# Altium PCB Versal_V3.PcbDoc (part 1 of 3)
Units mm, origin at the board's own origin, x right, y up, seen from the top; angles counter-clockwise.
Board outline 164.5 x 88.9 mm, 8 copper layers (Top Layer, Layer 2 [GND], Layer 3 [GND/OUT], Layer 4 [12V/GND], Layer 5 [GND/VOUT], Layer 6 [GND], Layer 7 [GND], Bottom Layer), stack 1.562 mm thick; 243 components, 69 nets, 695 pads, 1061 vias.
Unrouted connection lines stored in the file: 8.
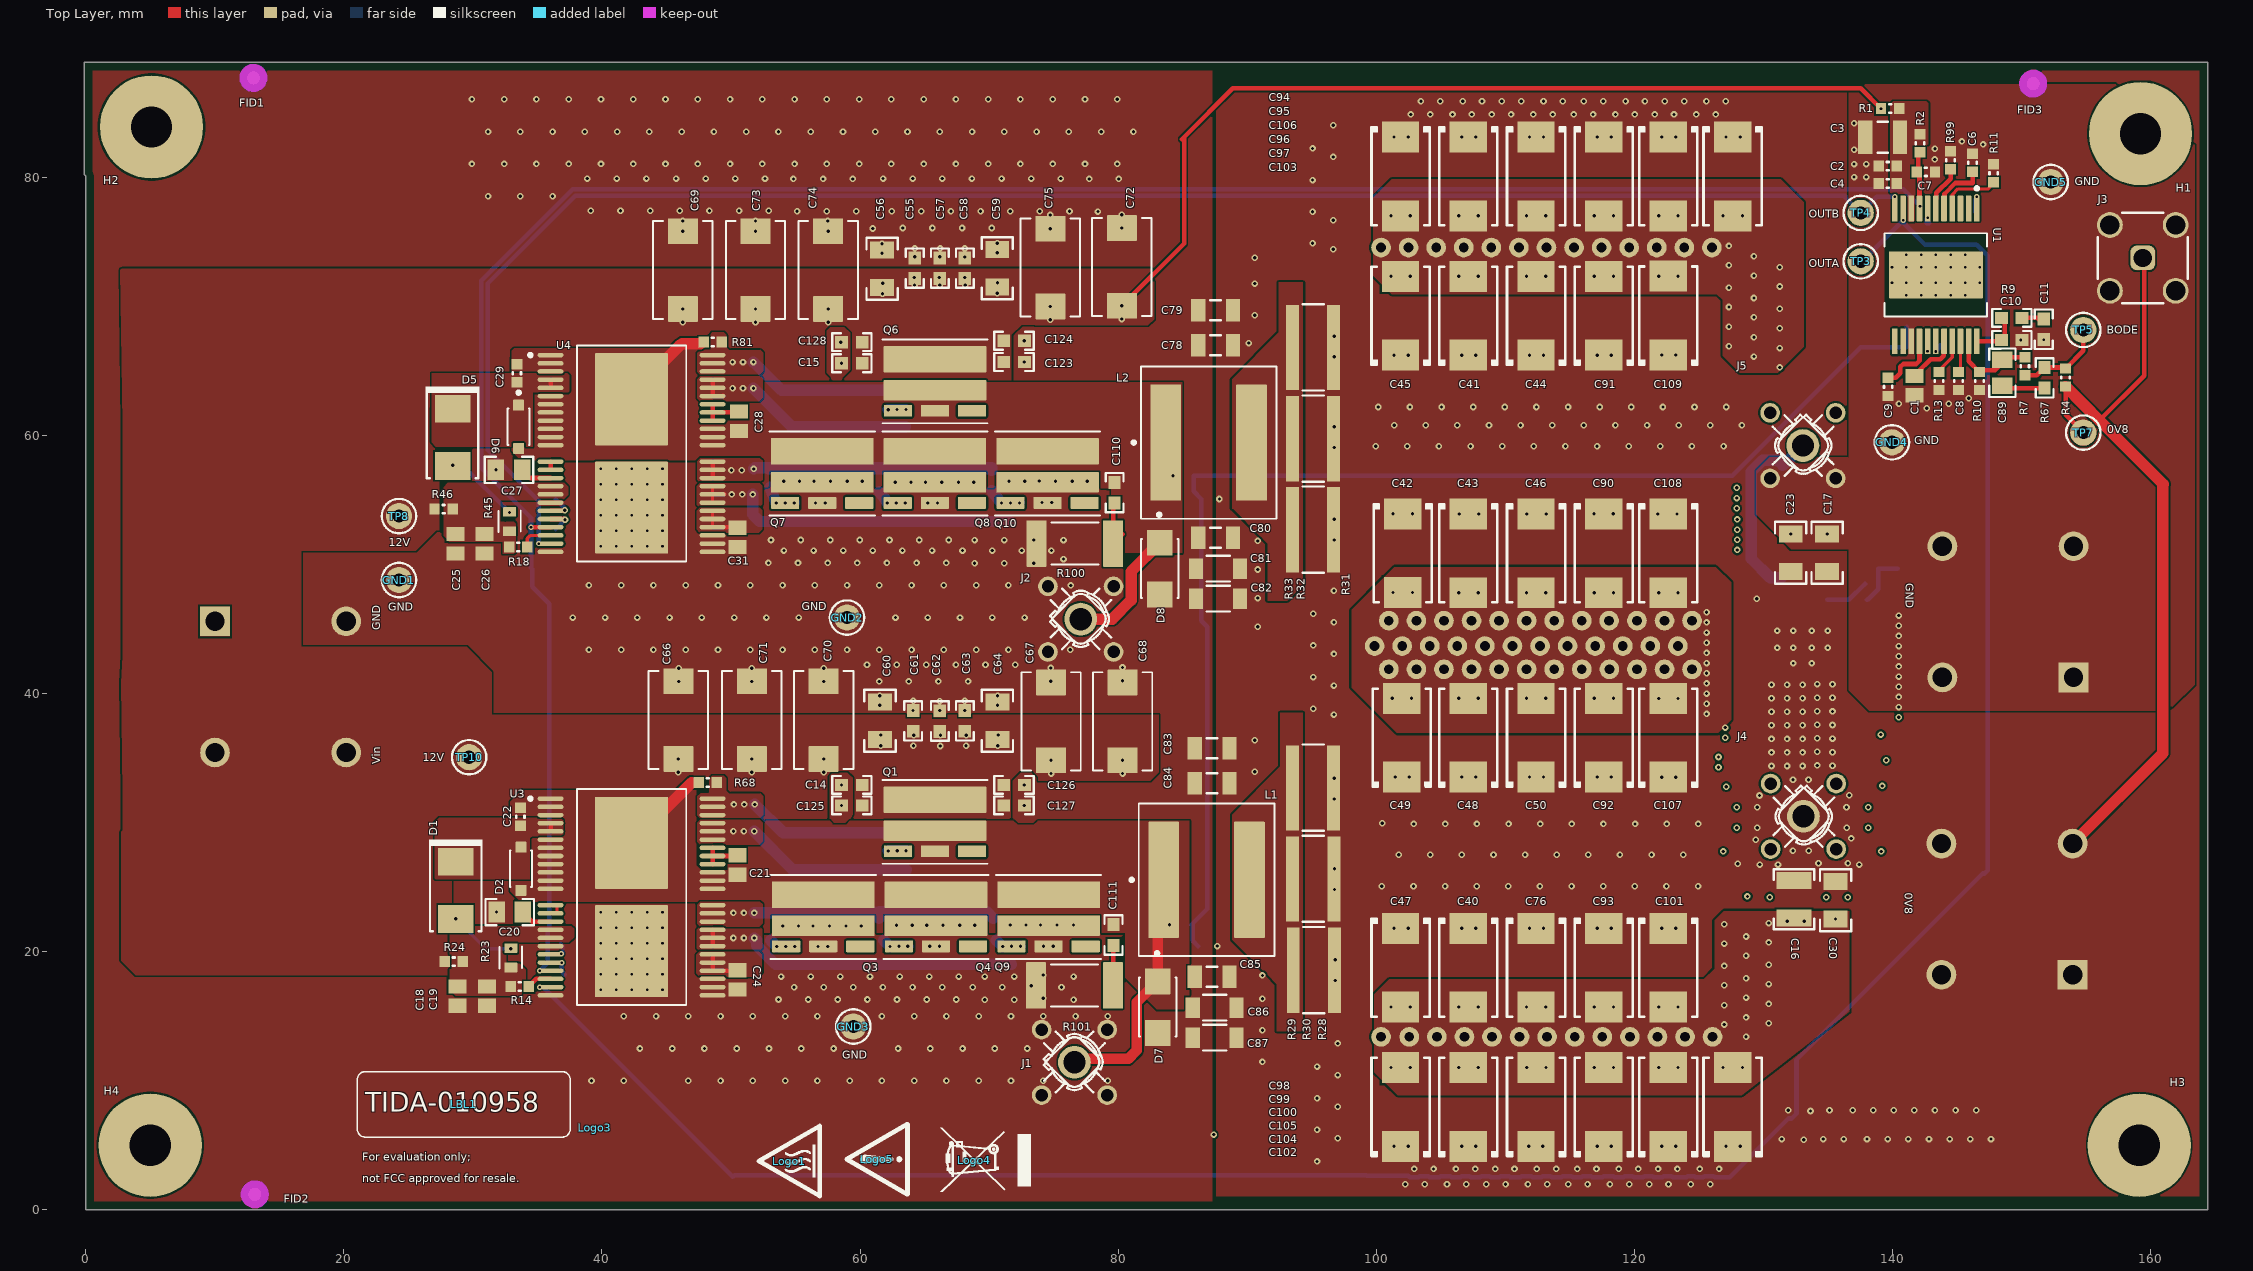
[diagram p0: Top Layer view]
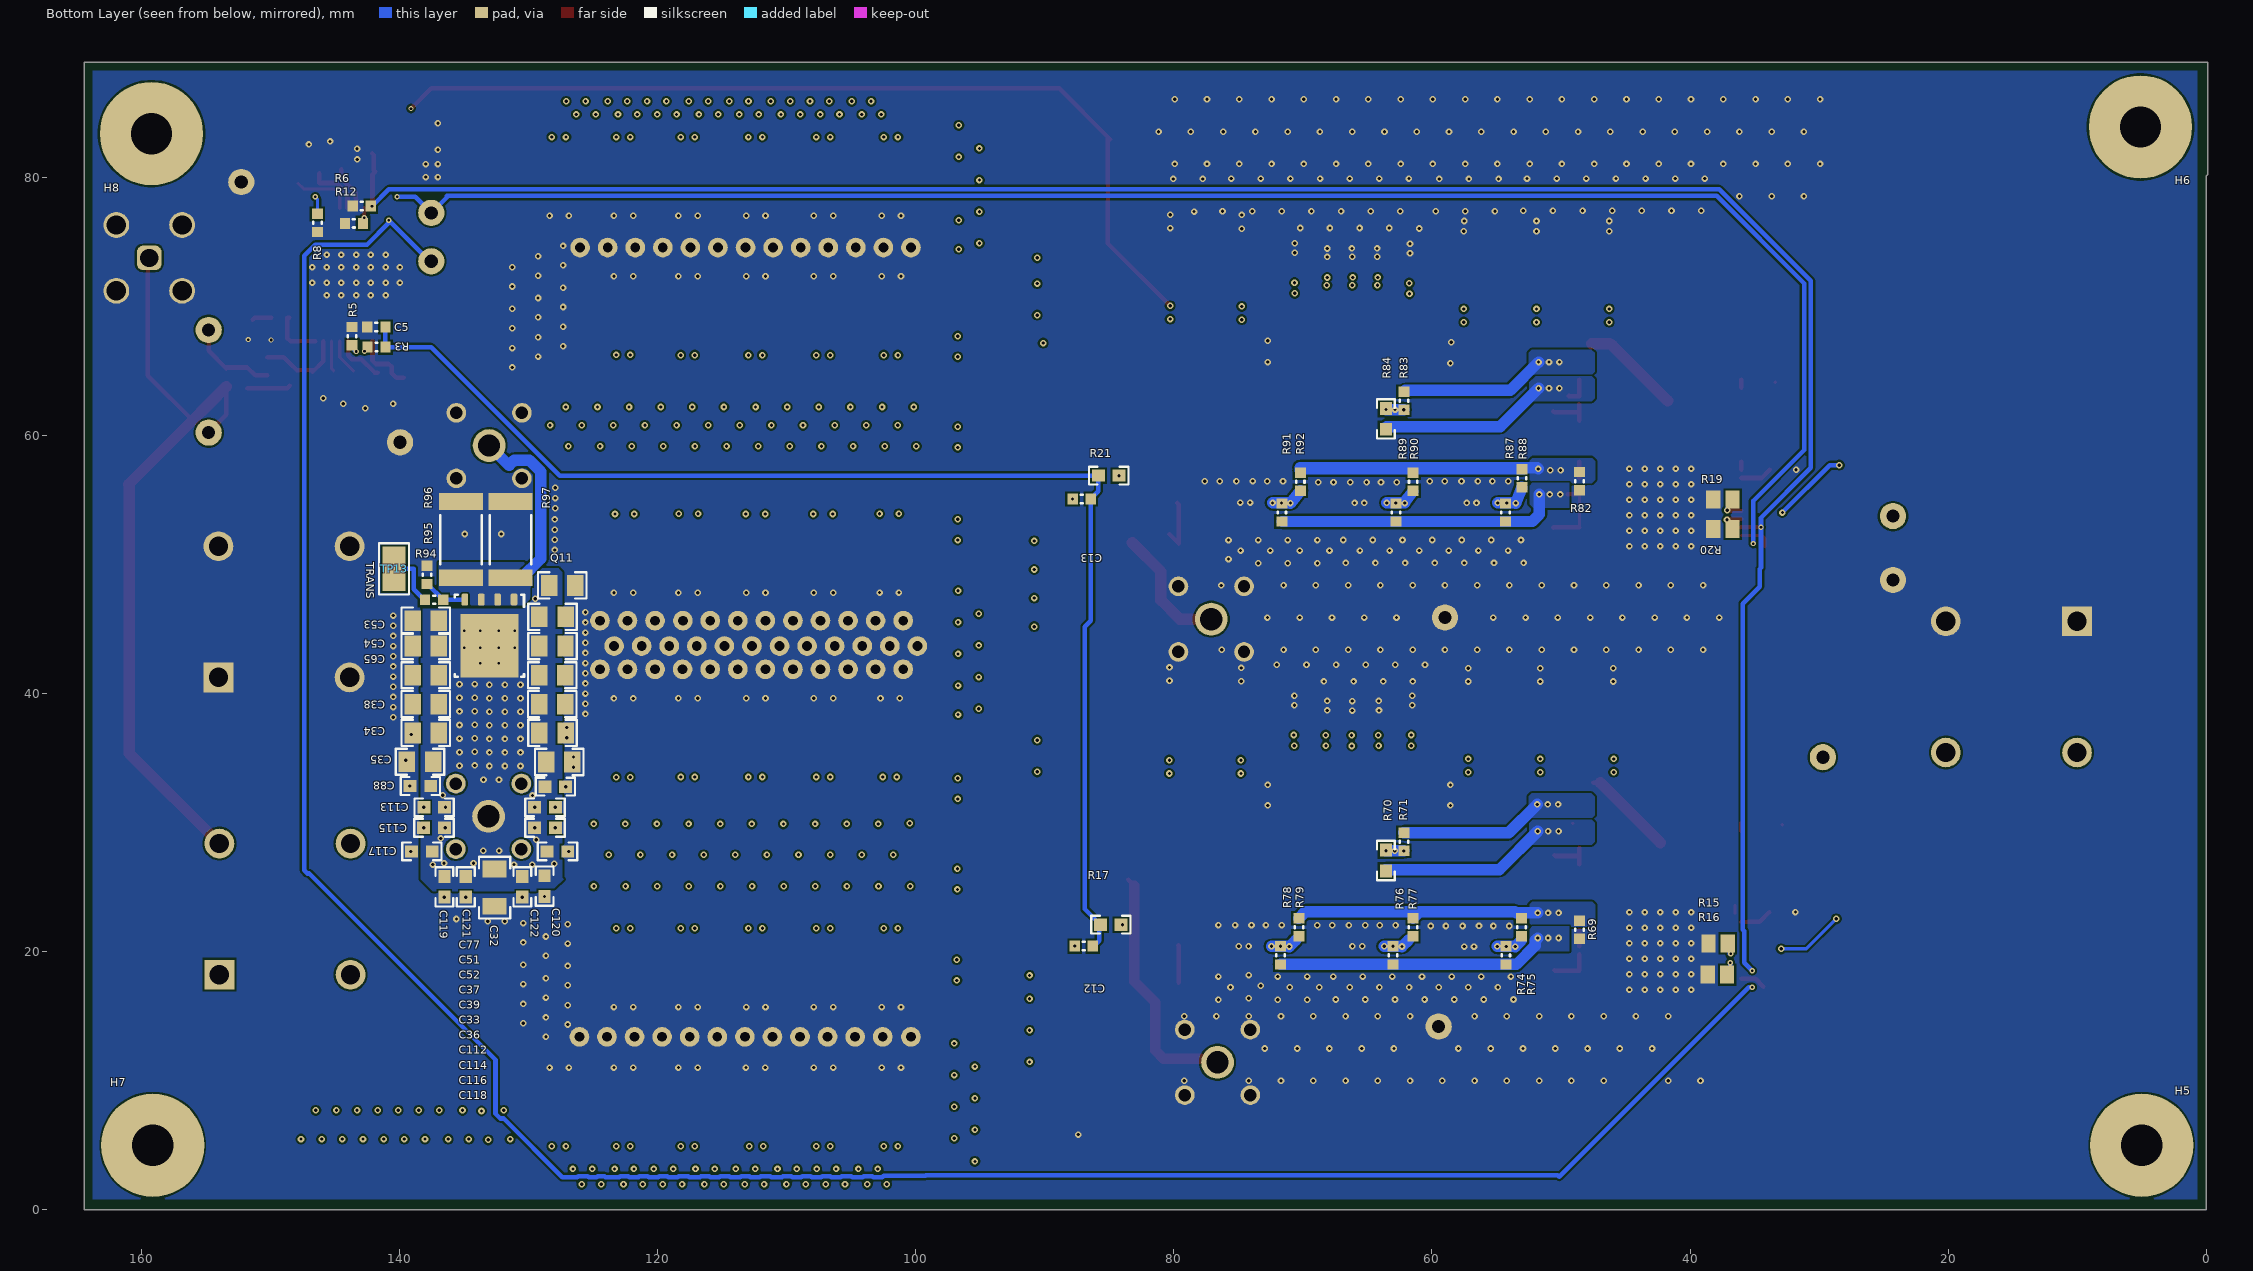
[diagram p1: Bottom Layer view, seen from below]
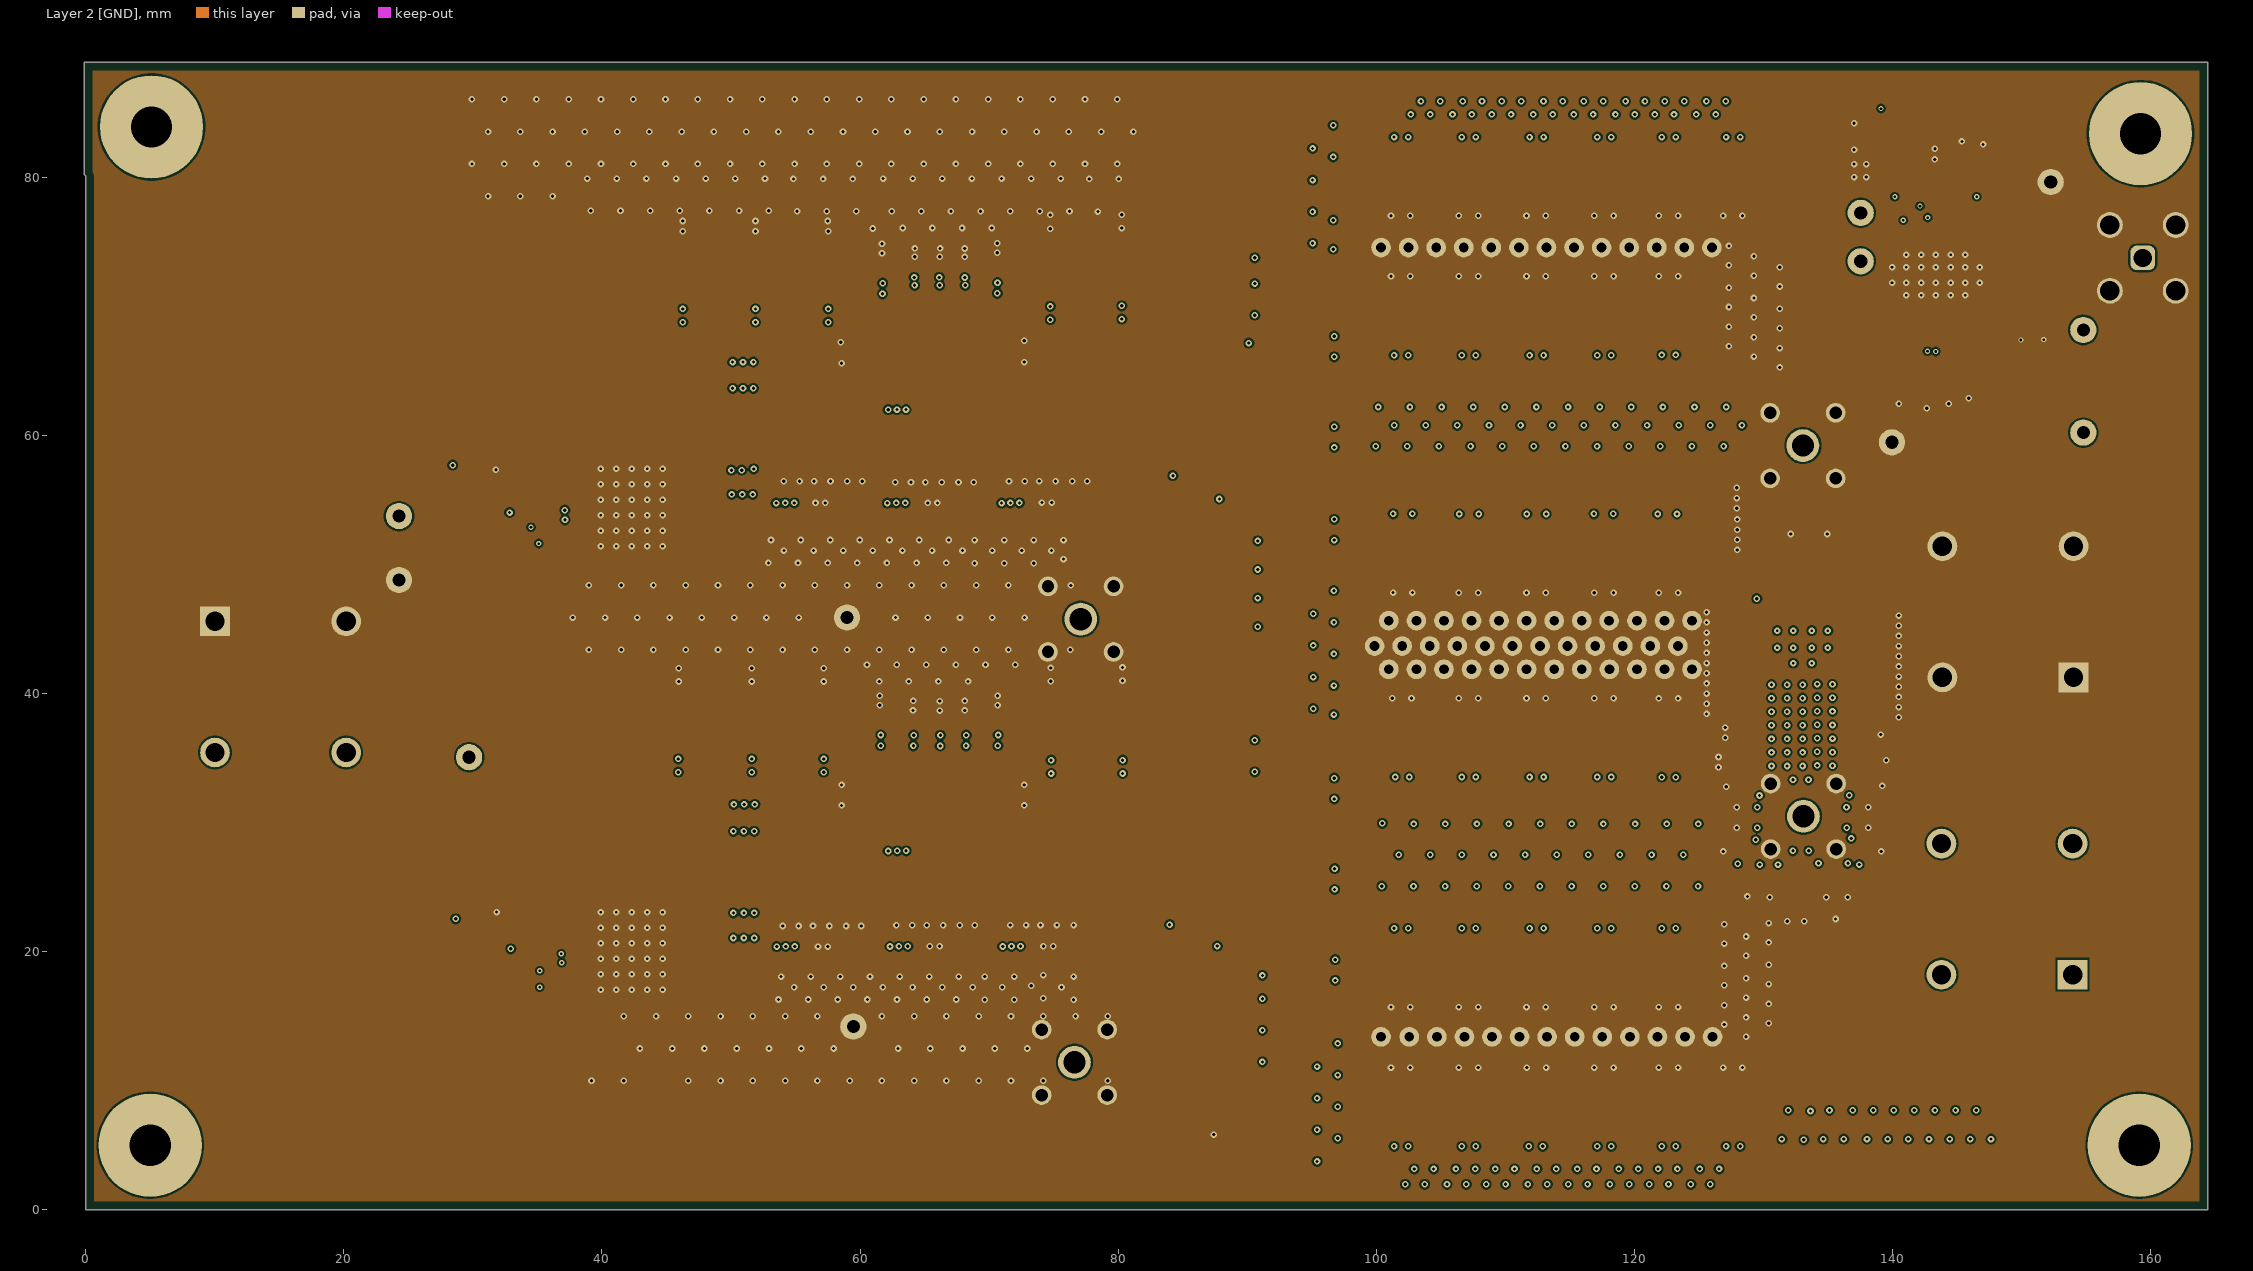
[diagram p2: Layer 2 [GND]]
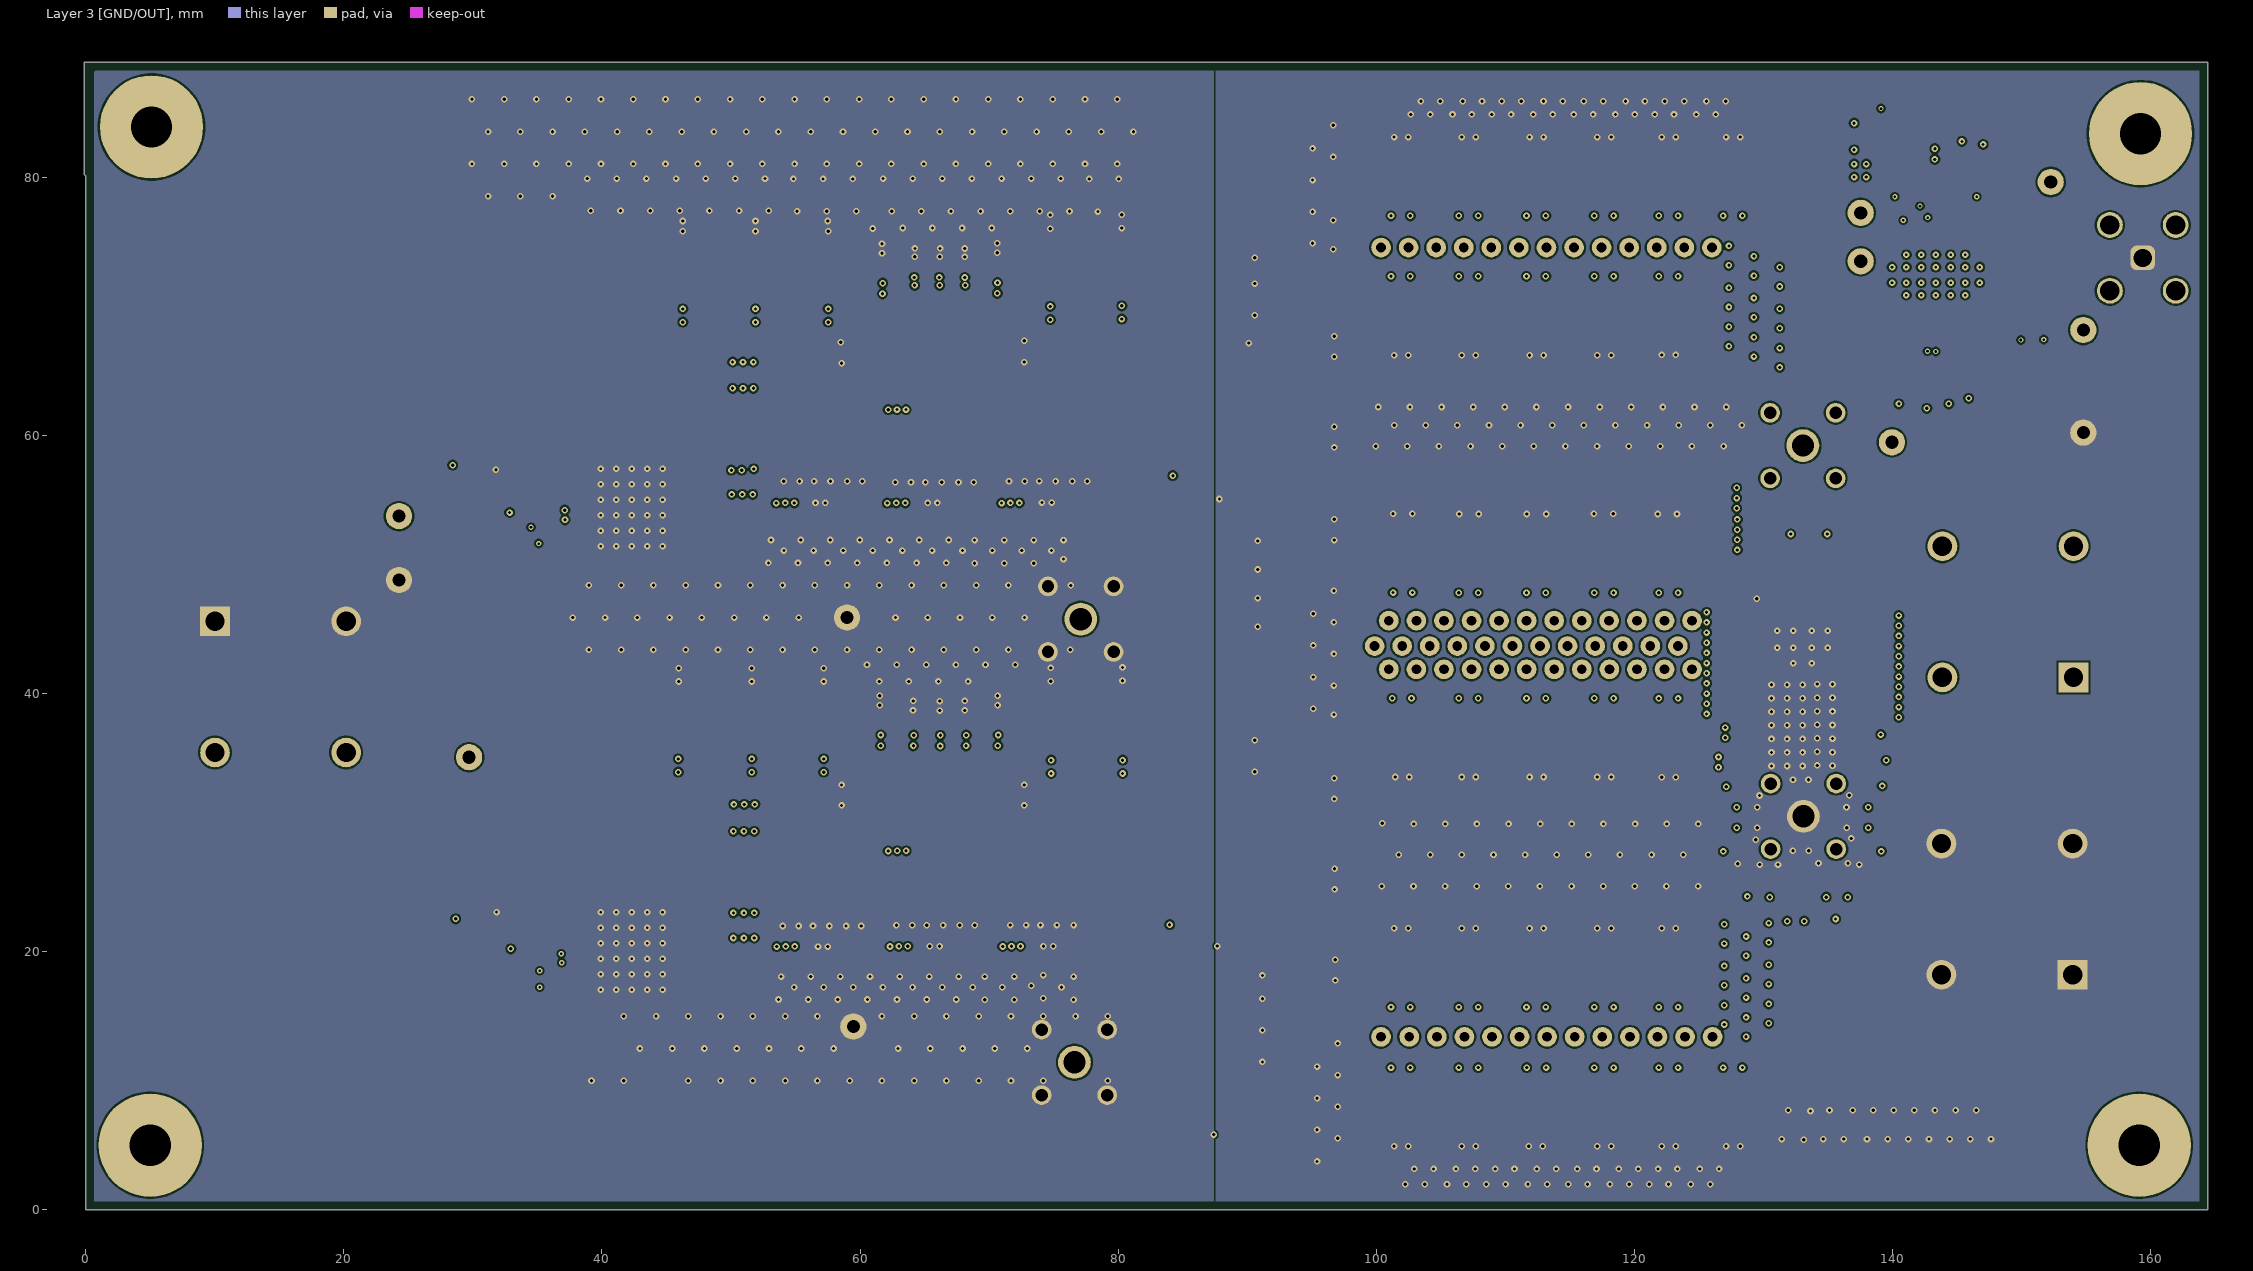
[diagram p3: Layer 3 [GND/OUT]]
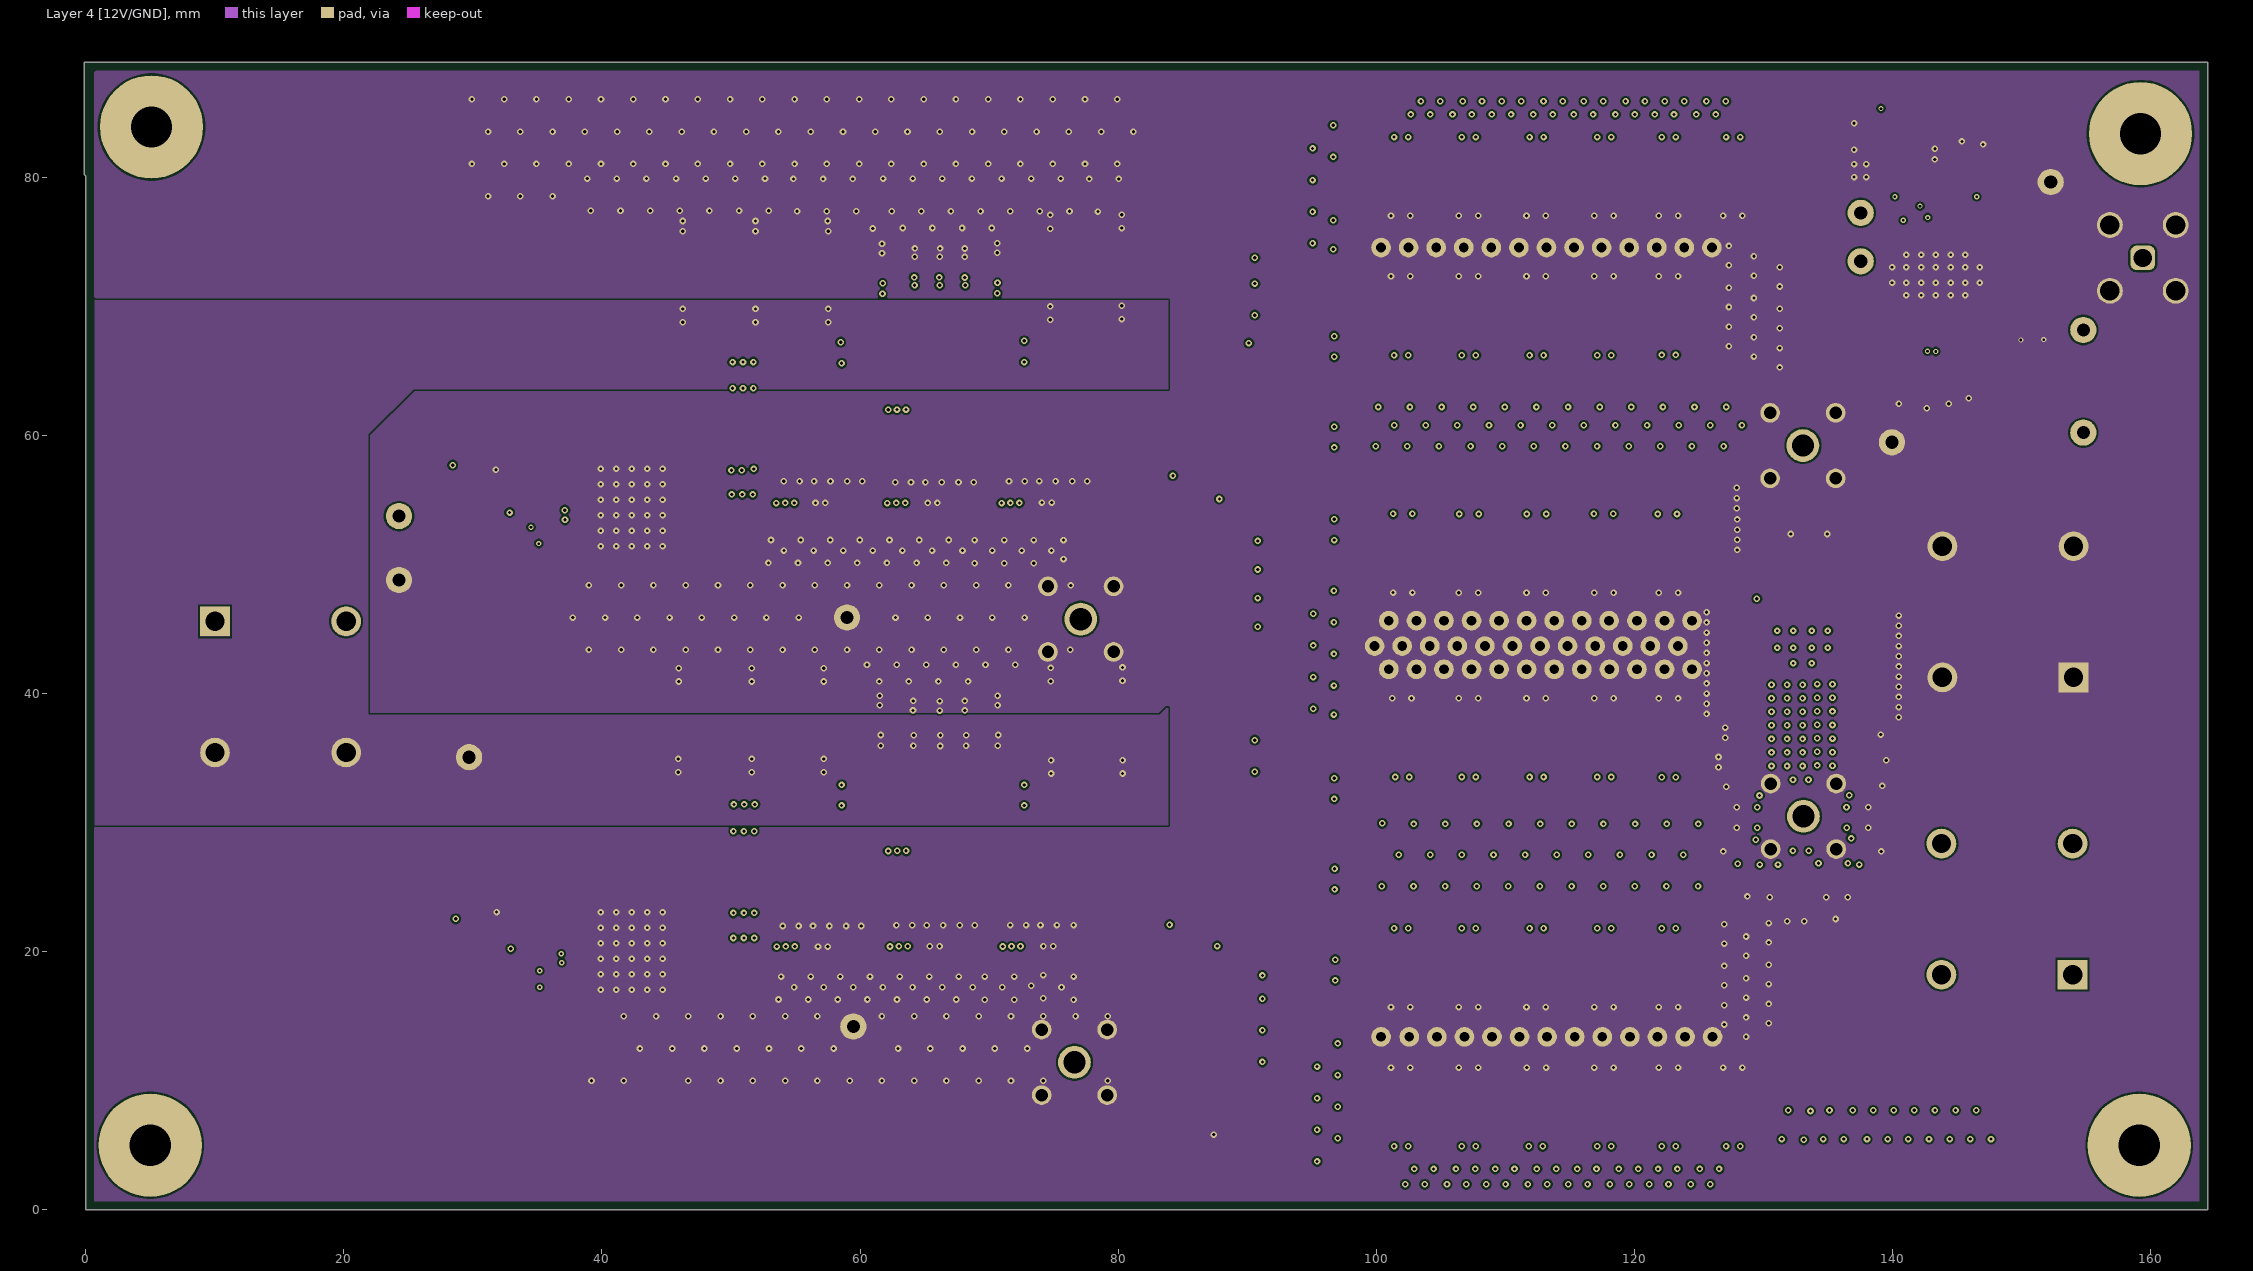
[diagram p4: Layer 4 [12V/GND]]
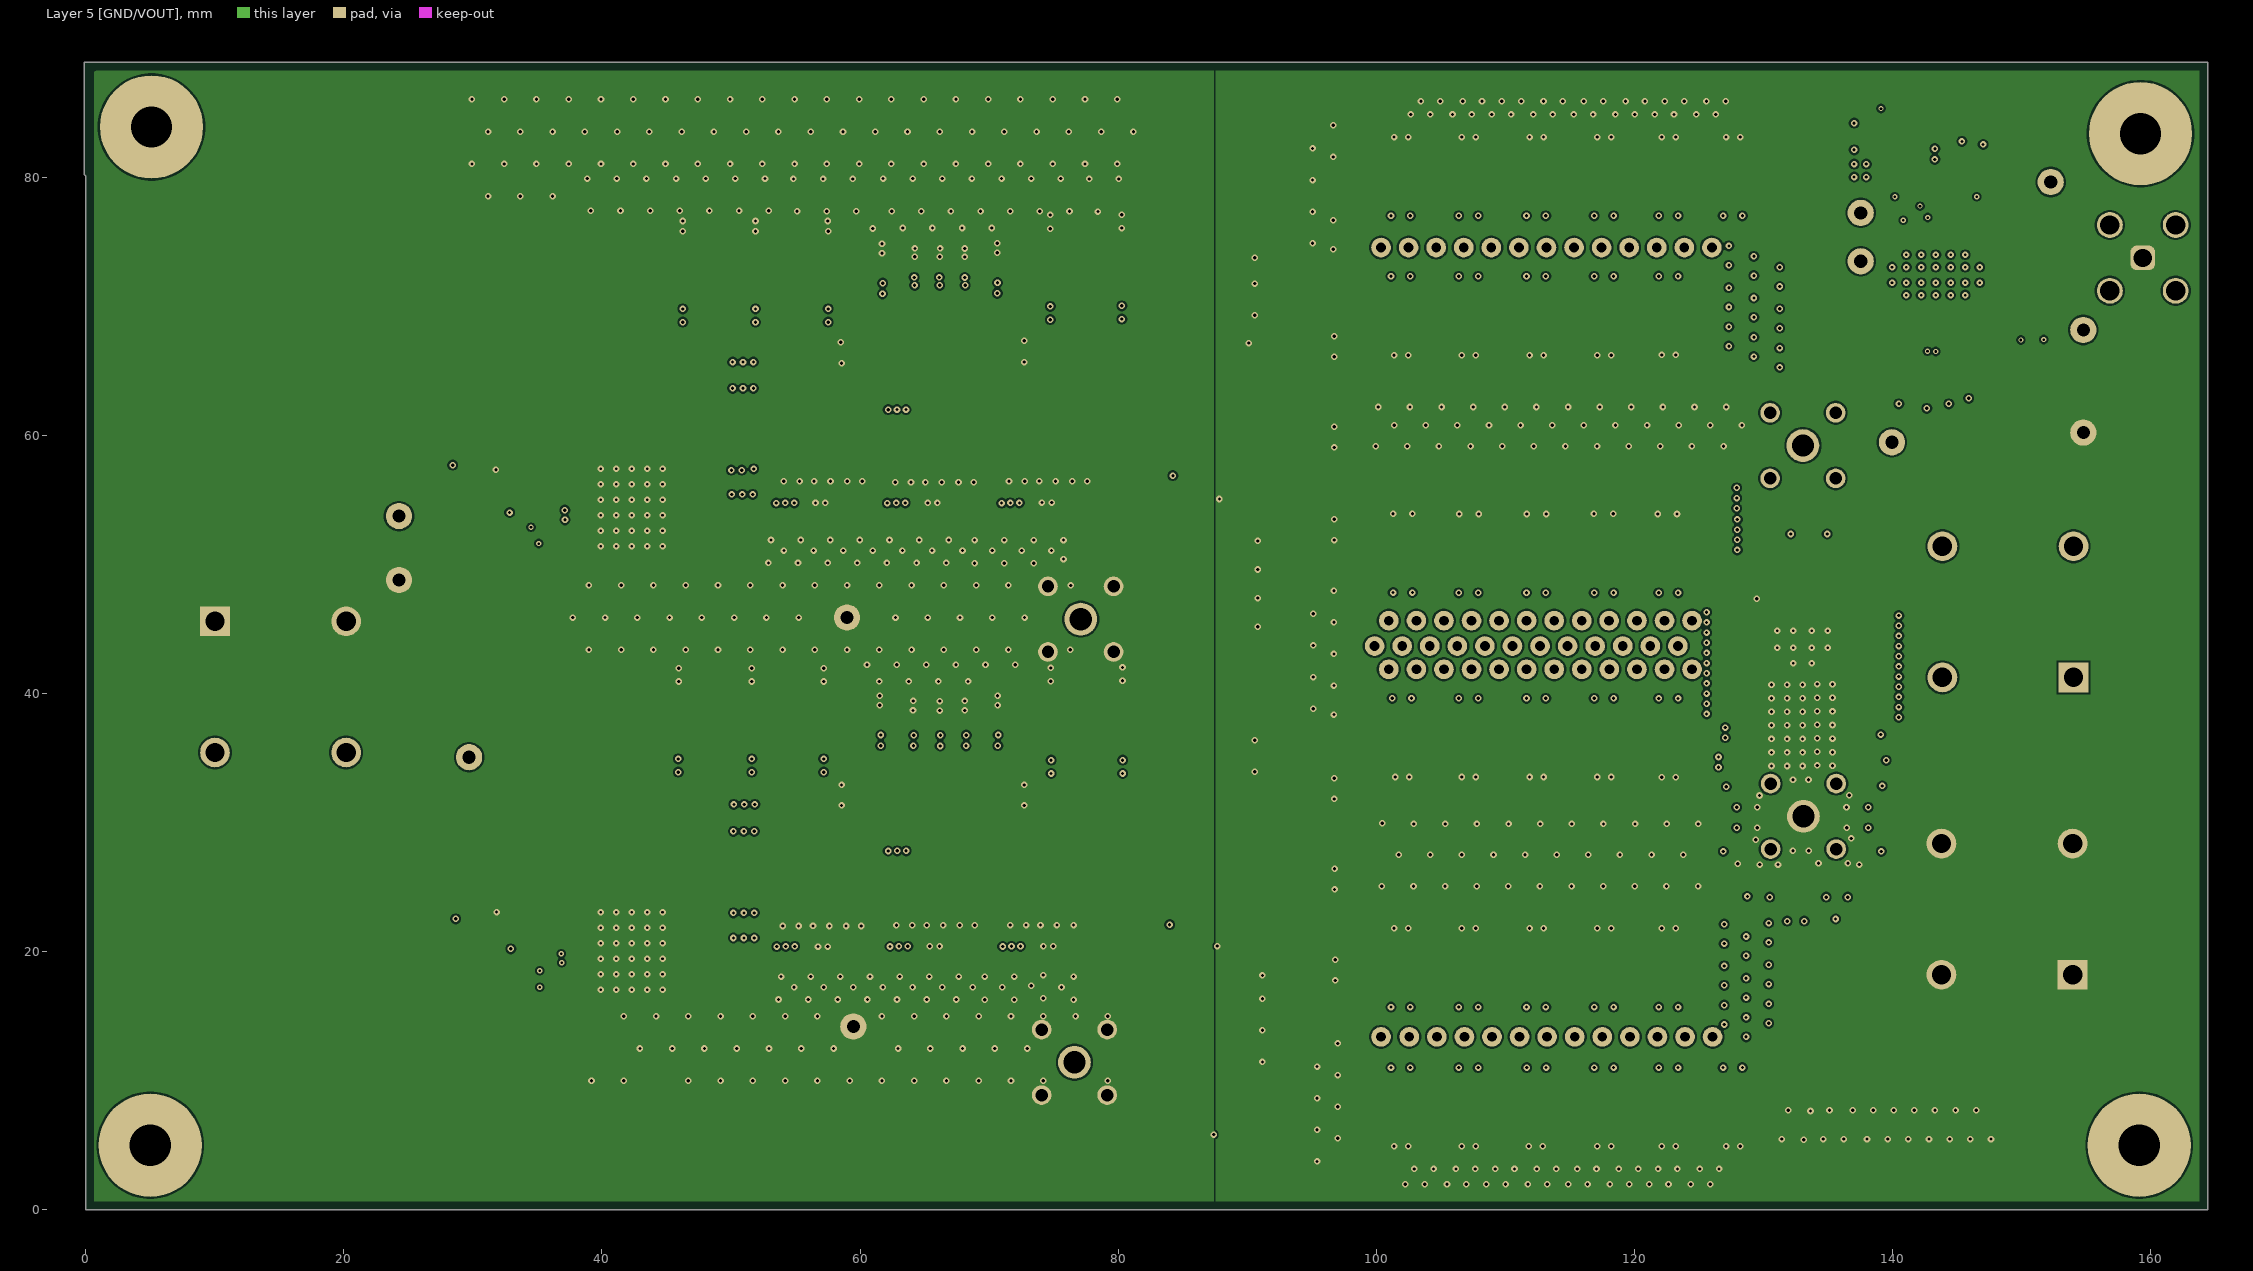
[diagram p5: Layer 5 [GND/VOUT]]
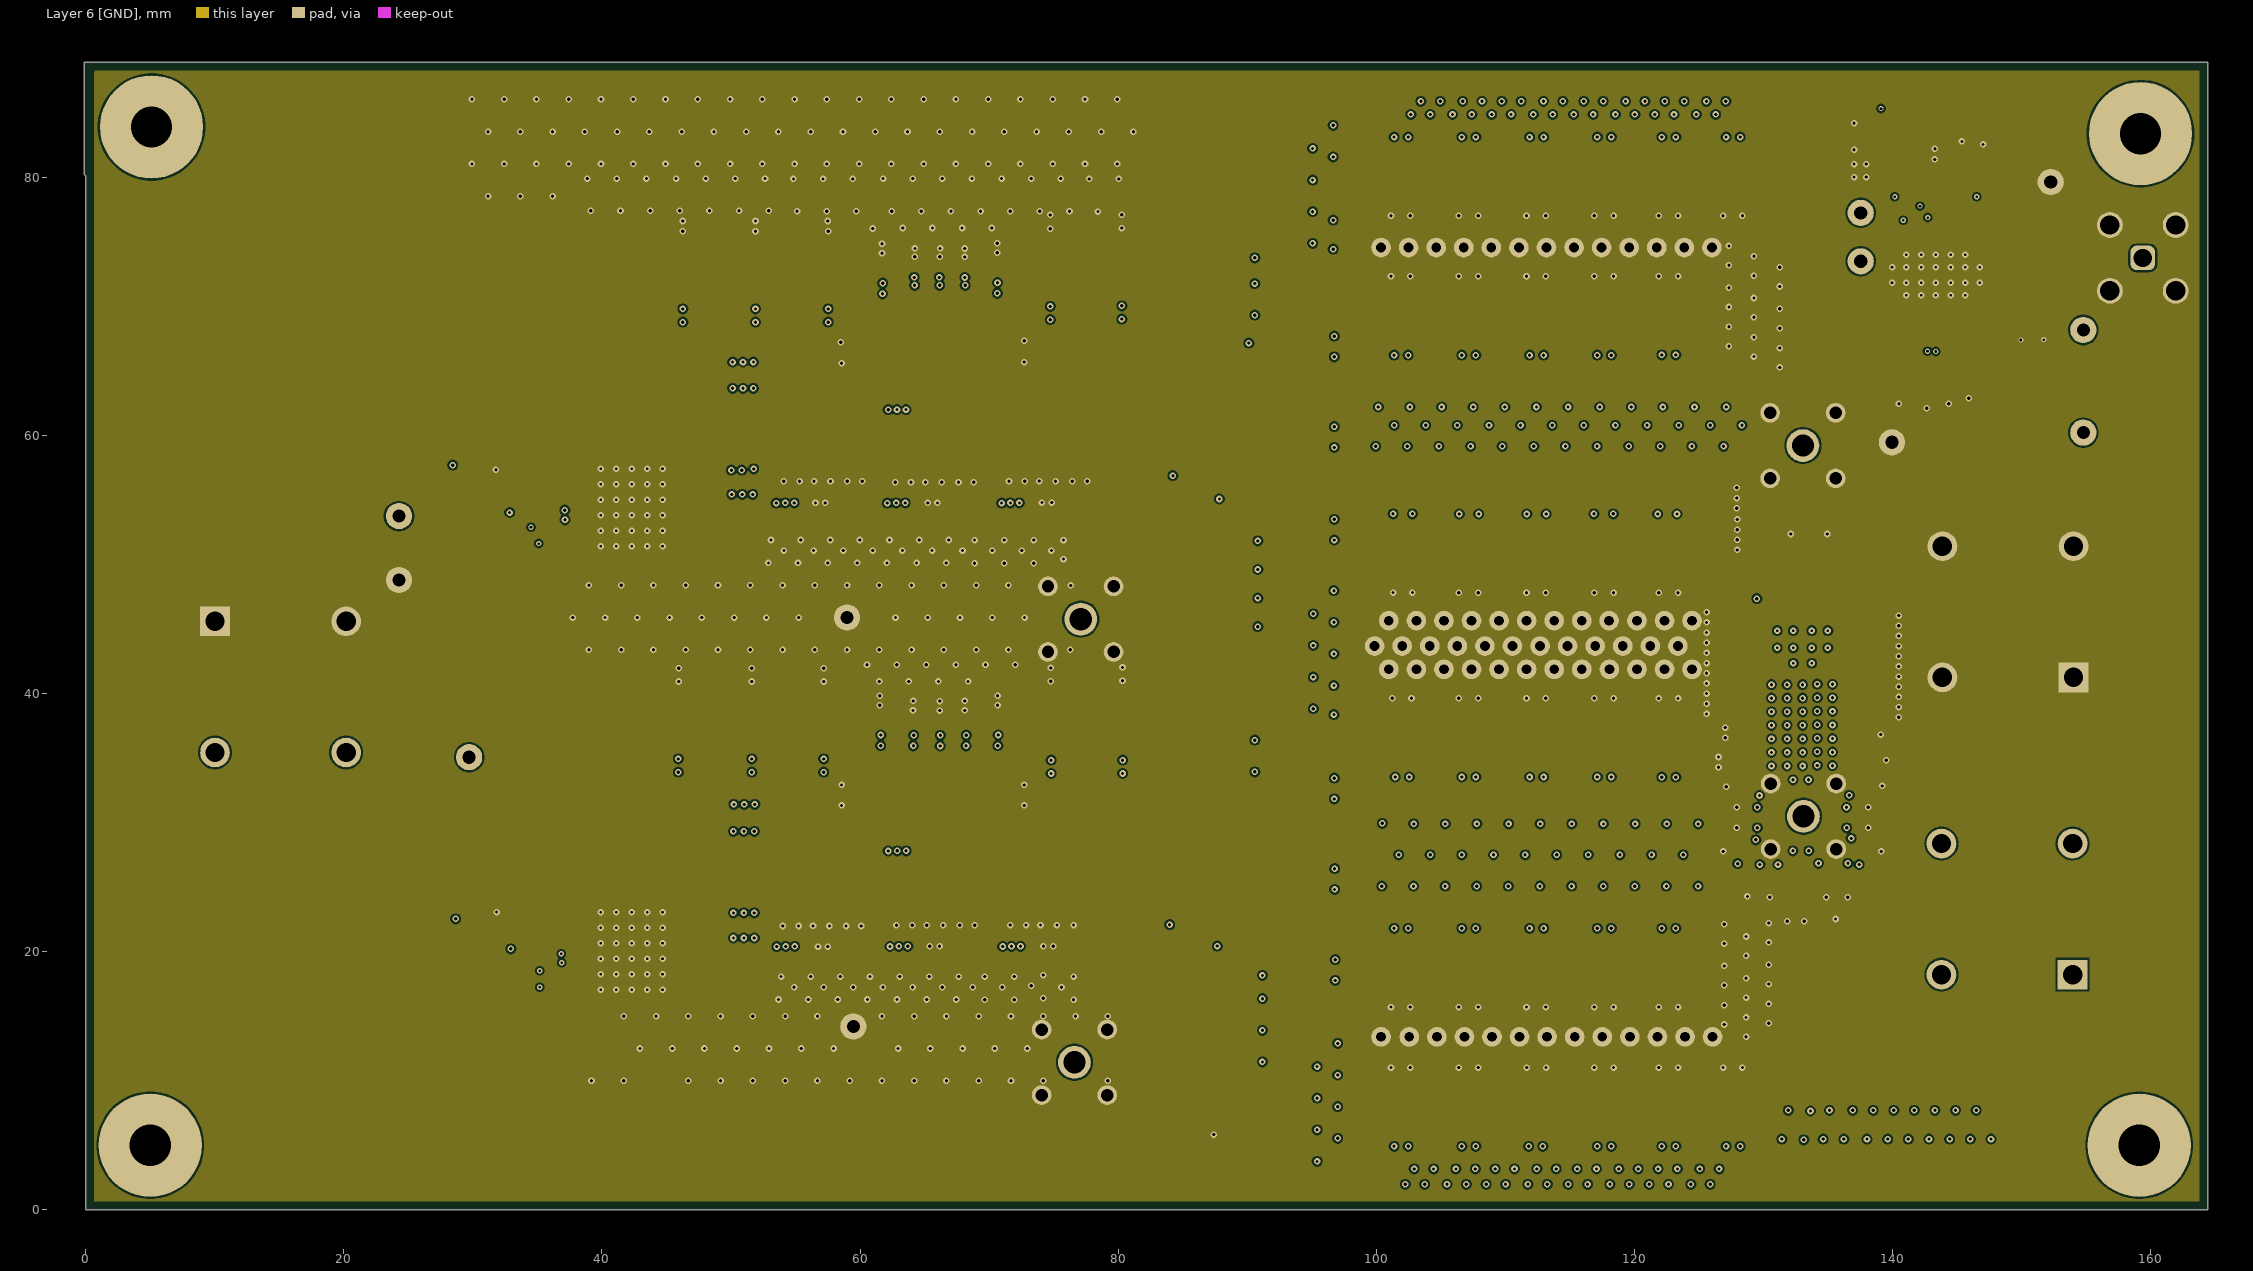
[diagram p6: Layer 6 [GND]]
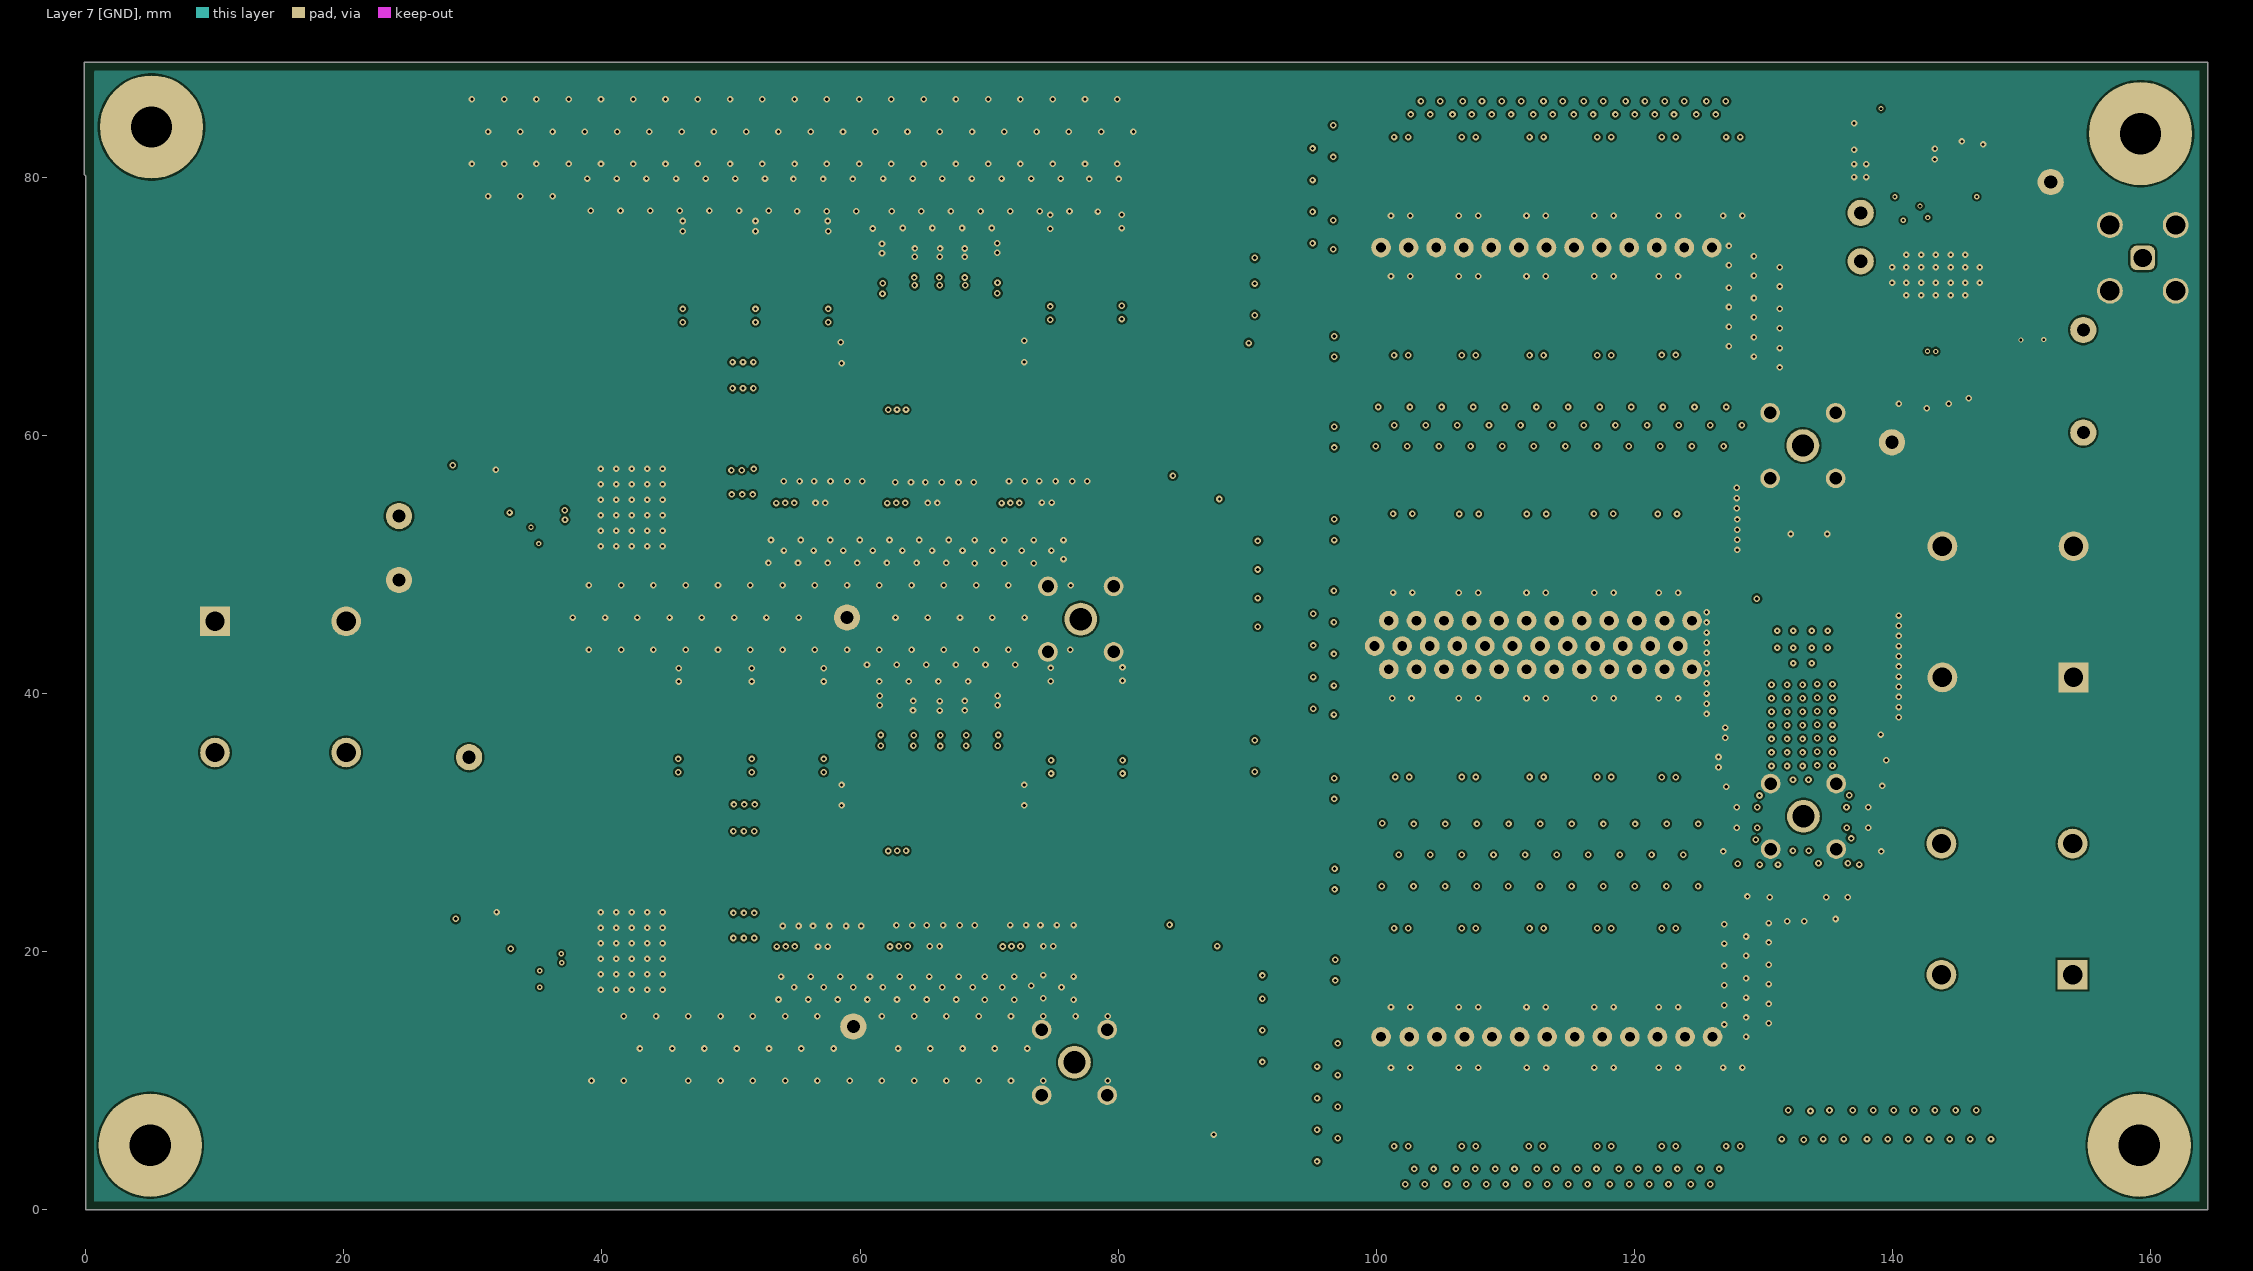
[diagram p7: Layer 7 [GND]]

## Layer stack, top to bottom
Top Solder: solder mask 0.0063, Solder Resist, Dk 3.5
Top Layer: signal copper 0.0439
Dielectric 5: prepreg 0.0446, PP-006, Dk 4.1
Layer 2 [GND]: signal copper 0.0439
Dielectric 3: prepreg 0.0446, PP-006, Dk 4.1
Layer 3 [GND/OUT]: signal copper 0.0439
Dielectric 1: prepreg 0.0446, PP-006, Dk 4.1
Layer 4 [12V/GND]: signal copper 0.0439
Dielectric1: core 0.9431, FR-4 High Tg, Dk 4.8
Layer 5 [GND/VOUT]: signal copper 0.0439
Dielectric 2: prepreg 0.0446, PP-006, Dk 4.1
Layer 6 [GND]: signal copper 0.0439
Dielectric 4: prepreg 0.0446, PP-006, Dk 4.1
Layer 7 [GND]: signal copper 0.0439
Dielectric 6: prepreg 0.0446, PP-006, Dk 4.1
Bottom Layer: signal copper 0.0439
Bottom Solder: solder mask 0.0063, Solder Resist, Dk 3.5

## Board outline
-0.1,88.9 164.4,88.9 164.4,0 0,0 0,80.1 -0.1,80.2

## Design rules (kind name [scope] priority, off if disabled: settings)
AcuteAngle [All] p1: minimum=4.50000000000000E+0001 checktracksonly=FALSE
AssemblyTestPointUsage [All] p1: valid=2
BoardOutlineClearance BoardOutlineClearance_CONNECTOR [HasFootprint('Emerson_142-0701-851') OR HasFootprint('ON-Shore_ED120_2DS') OR HasFootprint('FP-1929517_HDR2-MFG')] p1: gap=0.254 ignorepadtopadclearanceinfootprint=FALSE except(0: Arc-SplitContinuation Track-OutlineEdge Track-CavityEdge Track-CutoutEdge Track-SplitBarrior Track-SplitContinuation SMDPad-SplitContinuation THPad-SplitContinuation Via-SplitContinuation Fill-SplitContinuation Poly-SplitContinuation Region-SplitContinuation Text-SplitContinuation)
BoardOutlineClearance BoardOutlineClearance_MountingHoles [OnCopper and InComponentClass('Mounting Holes')] p2: gap=0.635 ignorepadtopadclearanceinfootprint=FALSE
BoardOutlineClearance BoardOutlineClearance_Poly [OnCopper and InPoly] p3: gap=0.635 ignorepadtopadclearanceinfootprint=FALSE
BoardOutlineClearance [OnCopper and Not InComponentClass('Logo') and not InComponentClass('FiducialMark') and not InRegion(1000,500,4000,800)] p4: gap=0.635 ignorepadtopadclearanceinfootprint=FALSE
Clearance Clearance_Logo [(InComponent('FID1') OR InComponent('FID2') OR InComponent('FID3'))] p1: gap=0 ignorepadtopadclearanceinfootprint=TRUE
Clearance Clearance_1 [All] p2: gap=0.152 ignorepadtopadclearanceinfootprint=FALSE except(0: Arc-Hole Track-Hole SMDPad-Hole THPad-Hole Via-Hole Fill-Hole Poly-Hole Region-Hole Text-Hole)
Clearance Clearance_Keepouts [((IsTrack Or IsArc) And Not InPoly) And IsFree and IsKeepOut vs ((IsTrack Or IsArc) And Not InPoly) And IsFree and IsKeepOut] p3: gap=0 ignorepadtopadclearanceinfootprint=FALSE
Clearance Clearance_Poly [InPolygon] p4: gap=0.152 ignorepadtopadclearanceinfootprint=FALSE
ComponentClearance ComponentClearance_MountingHoles_FiducialMarks [InComponentClass('Mounting Holes') vs InComponentClass('FiducialMark')] p1: gap=0.762 collisioncheckmode=3 verticalgap=0.254 showdistances=FALSE
ComponentClearance ComponentClearance_Shunt [InComponentClass('Header') vs InComponentClass('Shunt')] p2: gap=0 collisioncheckmode=3 verticalgap=0 showdistances=FALSE
ComponentClearance ComponentClearance_Logo [InComponentClass('Logo')] p3: gap=0.254 collisioncheckmode=3 verticalgap=0.254 showdistances=FALSE
ComponentClearance ComponentClearance_ScrewToNut [(HasFootprint('NY PMS 440 0025 PH')) vs (HasFootprint('Keystone_1902C'))] p4: gap=0.127 collisioncheckmode=3 verticalgap=0.254 showdistances=FALSE
ComponentClearance ComponentClearance_MountingHoles [InComponentClass('Mounting Holes')] p5: gap=2.54 collisioncheckmode=3 verticalgap=2540 showdistances=TRUE
ComponentClearance ComponentClearance_SmallPassives [HasFootprint('0201*') or HasFootprint('0402*') or HasFootprint('0508') or HasFootprint('0603*') or HasFootprint('0612') or HasFootprint('0805*') or HasFootprint('0815*') or HasFootprint('0830*') or HasFootprint('1206*') or HasFootprint('1210*') or HasFootprint('1808*') or HasFootprint('1812*') or HasFootprint('1825*') or HasFootprint('2010*') or HasFootprint('2220*') or HasFootprint('2225*') or HasFootprint('2512*') or HasFootprint('2728*') or HasFootprint('3518*') vs HasFootprint('0201*') or HasFootprint('0402*') or HasFootprint('0508') or HasFootprint('0603*') or HasFootprint('0612') or HasFootprint('0805*') or HasFootprint('0815*') or HasFootprint('0830*') or HasFootprint('1206*') or HasFootprint('1210*') or HasFootprint('1808*') or HasFootprint('1812*') or HasFootprint('1825*') or HasFootprint('2010*') or HasFootprint('2220*') or HasFootprint('2225*') or HasFootprint('2512*') or HasFootprint('2728*') or HasFootprint('3518*')] p6: gap=0.356 collisioncheckmode=3 verticalgap=0.254 showdistances=FALSE
ComponentClearance ComponentClearance_THtoSMT [IsThruComponent vs IsSMTComponent] p7: gap=0.381 collisioncheckmode=3 verticalgap=0.762 showdistances=FALSE
ComponentClearance ComponentClearance_THtoTH [IsThruComponent vs IsThruComponent] p8: gap=0.381 collisioncheckmode=3 verticalgap=0.762 showdistances=FALSE
ComponentClearance [All] p9: gap=0.381 collisioncheckmode=3 verticalgap=0.254 showdistances=FALSE
DiffPairsRouting [All] p1: maxlimit=2.54 minlimit=0.254 mostfreqgap=0.254 toplayer_minwidth=0.381 toplayer_maxwidth=0.381 toplayer_prefwidth=0.381 midlayer1_minwidth=0.381 midlayer1_maxwidth=0.381 midlayer1_prefwidth=0.381 midlayer2_minwidth=0.381 midlayer2_maxwidth=0.381 midlayer2_prefwidth=0.381 midlayer3_minwidth=0.381 midlayer3_maxwidth=0.381 midlayer3_prefwidth=0.381 midlayer4_minwidth=0.381 midlayer4_maxwidth=0.381 midlayer4_prefwidth=0.381 midlayer5_minwidth=0.381 midlayer5_maxwidth=0.381 midlayer5_prefwidth=0.381 midlayer6_minwidth=0.381 midlayer6_maxwidth=0.381 midlayer6_prefwidth=0.381 bottomlayer_minwidth=0.381 bottomlayer_maxwidth=0.381 bottomlayer_prefwidth=0.381 maxuncoupledlength=25.4
FabricationTestPointUsage TestPointUsage [All] p1: valid=2 allowmultiple=FALSE
FabricationTestpoint Testpoint [All] p1: side=3 testpointundercomponent=TRUE minsize=1.016 maxsize=2.54 preferedsize=1.524 minholesize=0 maxholesize=1.016 preferedholesize=0.813 testpointgrid=0.025 allowsidetop=TRUE allowsidebottom=TRUE usegrid=TRUE gridtolerance=0
FanoutControl Fanout_LCC [IsLCC] p1: bgadir=Out bgaviamode=Centered fanoutstyle=Auto fanoutdirection=Alternating viagrid=0.025 // Fanout_LCC (Default Rule)
FanoutControl Fanout_BGA [IsBGA] p2: bgadir=Out bgaviamode=Centered fanoutstyle=Auto fanoutdirection=Alternating viagrid=0.025 // Fanout_BGA (Default Rule)
FanoutControl Fanout_Default [All] p4: bgadir=Out bgaviamode=Centered fanoutstyle=Auto fanoutdirection=Alternating viagrid=0.025 // Fanout_Default (Default Rule)
FanoutControl Fanout_Small [(CompPinCount < 5)] p5: bgadir=Out bgaviamode=Centered fanoutstyle=Auto fanoutdirection=OutThenIn viagrid=0.025 // Fanout_Small (Default Rule)
HoleSize HoleSize_TEMP [All] p1: absolutevalues=TRUE maxlimit=6.375 minlimit=0.2 maxpercent=80.000 minpercent=20.000
HoleSize [All] p2: absolutevalues=TRUE maxlimit=6.375 minlimit=0.254 maxpercent=80.000 minpercent=20.000
MinimumAnnularRing MinimumAnnularRing_ThermalPadVias [IsVia and InAnyComponent] p1: minimumring=0.102
MinimumAnnularRing [All] p2: minimumring=0.102
MinimumSolderMaskSliver MinimumSolderMaskSliver_Logo [InComponentClass('Logo') vs InComponentClass('Logo')] p1: minsoldermaskwidth=0.018
MinimumSolderMaskSliver MinimumSolderMaskSliver_Temp [All] p2: minsoldermaskwidth=0.005
MinimumSolderMaskSliver [All] p3: minsoldermaskwidth=0.1
PlaneConnect [All] p1: planeconnectstyle=Direct reliefexpansion=0.254 reliefentries=4 reliefconductorwidth=0.254 reliefairgap=0.254
PolygonConnect [All] p1: connectstyle=Direct reliefconductorwidth=0.254 reliefentries=4 polygonreliefangle="90 Angle" airgapwidth=0.254
RoutingVias ThermalPadVias_TEMP [IsVia and InAnyComponent] p1: holewidth=0.254 width=0.5 viastyle="Through Hole" minholewidth=0.2 minwidth=0.5 maxholewidth=0.508 maxwidth=0.813
RoutingVias ThermalPadVias [IsVia and InAnyComponent] p2: holewidth=0.254 width=0.508 viastyle="Through Hole" minholewidth=0.254 minwidth=0.5 maxholewidth=0.33 maxwidth=0.6
RoutingVias RoutingVias_temp [All] p3: holewidth=0.406 width=0.813 viastyle="Through Hole" minholewidth=0.2 minwidth=0.483 maxholewidth=1.27 maxwidth=2.54
RoutingVias [All] p4: holewidth=0.406 width=0.813 viastyle="Through Hole" minholewidth=0.254 minwidth=0.508 maxholewidth=1.27 maxwidth=2.54
SilkToBoardRegionClearance [Not ((IsComment or IsDesignator) And (Hide <> 'False')) and not InRegion(1000,500,4000,800)] p1:
SilkToSilkClearance SilkToSilkClearance_Pb-FreeLogo [(HasFootprint('Pb-Free_Overlay_Medium') OR HasFootprint('Pb-Free_Overlay_Small')) vs (HasFootprint('Pb-Free_Overlay_Medium') OR HasFootprint('Pb-Free_Overlay_Small'))] p1: silktosilkclearance=0
SilkToSilkClearance SilkToSilkClearance_Temp [All] p2: silktosilkclearance=0.003
SilkToSilkClearance [All] p3: silktosilkclearance=0.076
SilkToSolderMaskClearance SilkToComponentPadClearance_TEMP [IsPad and InAnycomponent] p1: minsilkscreentomaskgap=0.005 clearancetoexposedcopper=TRUE
SilkToSolderMaskClearance SilkToComponentPadClearance [IsPad and InAnycomponent] p2: minsilkscreentomaskgap=0.102 clearancetoexposedcopper=TRUE
SilkToSolderMaskClearance "Silk to Solder Mask Opening_TEMP" [All] p3: minsilkscreentomaskgap=0 clearancetoexposedcopper=FALSE
SilkToSolderMaskClearance "Silk to Solder Mask Opening" [All] p4: minsilkscreentomaskgap=0.076 clearancetoexposedcopper=FALSE
SolderMaskExpansion [All] p1: expansion=0.05 istentingtop=FALSE
Width [All] p1: maxlimit=2.54 minlimit=0.152 preferedwidth=0.254 checkconnectedcopper=TRUE
15 further rules are at their usual default settings.

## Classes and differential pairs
component class "Mounting Holes": H1 H2 H3 H4
component class Label: LBL1
component class FiducialMark: FID1 FID2 FID3
component class Hardware: !PCB FID1 FID2 FID3 H1 H2 H3 H4 H5 H6 H7 H8 LBL1 Logo1 Logo3 Logo4 Logo5
component class 12V_to_0V8_version3: 0V8 C1 C2 C3 C4 C5 C6 C7 C8 C9 C10 C11 C12 C13 C14 C15 C16 C17 C18 C19 C20 C21 C22 C23 C24 C25 C26 C27 C28 C29 C30 C31 C32 C33 C34 C35 C36 C37 C38 C39 C40 C41 C42 C43 C44 C45 C46 C47 C48 C49 C50 C51 C52 C53 C54 C55 C56 C57 C58 C59 C60 C61 C62 C63 C64 C65 C66 C67 C68 C69 C70 C71 C72 C73 C74 C75 C76 C77 C78 C79 C80 C81 C82 C83 C84 C85 C86 C87 C88 C89 C90 C91 C92 C93 C94 C95 C96 C97 C98 C99 C100 C101 C102 C103 C104 C105 C106 C107 C108 C109 C110 C111 C112 C113 C114 C115 C116 C117 C118 C119 C120 C121 C122 C123 C124 C125 C126 C127 C128 D1 D2 D5 D6 D7 D8 GND GND1 GND2 GND3 GND4 GND5 J1 J2 J3 J4 J5 L1 L2 Q1 Q3 Q4 Q6 Q7 Q8 Q9 Q10 Q11 R1 R2 R3 R4 R5 R6 R7 R8 R9 R10 R11 R12 R13 R14 R15 R16 R17 R18 R19 R20 R21 R23 R24 R28 R29 R30 R31 R32 R33 R45 R46 R67 R68 R69 R70 R71 R74 R75 R76 R77 R78 R79 R81 R82 R83 R84 R87 R88 R89 R90 R91 R92 R94 R95 R96 R97 R99 R100 R101 TP3 TP4 TP5 TP7 TP8 TP10 TP13 U1 U3 U4 Vin Vout

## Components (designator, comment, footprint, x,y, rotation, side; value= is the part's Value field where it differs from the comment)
0V8 "1929517" FP-1929517_HDR2-MFG 151.6,23.4 r90 top
C1 "C2012X5R1H474K125AB" 0805L 141.677,63.854 r270 top value=0.47uF
C2 "CGA3E1X7R1C105K080AC" 0603L 139.611,80.859 r180 top value=1uF
C3 "GRM32ER71H106KA12L" 1210_270L 139.229,83.108 r180 top value=10uF
C4 "C0603C104K5RACAUTO" 0603L 139.611,79.518 r180 top value=0.1uF
C5 "06033C101KAT2A" 0603L 141.776,68.397 r180 bottom value=100pF
C6 "GCM188R72A472KA37D" 0603L 146.196,81.118 r90 top value=4700pF
C7 "C0603C104K5RACAUTO" 0603L 142.576,80.423 r0 top value=0.1uF
C8 "CGA3E3X7S2A333K080AB" 0603L 145.097,64.217 r90 top value=0.033uF
C9 "CGA3E1X7R1C105K080AC" 0603L 139.656,63.759 r90 top value=1uF
C10 "GRM1885C2A820JA01D" 0603 149.236,67.391 r0 top value=82pF
C11 "CGA3E2X7R2A103K080AA" 0603 151.707,68.225 r270 top value=0.01uF
C12 "06035C104KAZ2A" 0603L 86.977,20.436 r180 bottom value=0.1uF
C13 "06035C104KAZ2A" 0603L 87.137,55.074 r180 bottom value=0.1uF
C14 "GCM188R71E104KA57D" 0603 59.365,32.922 r180 top value=0.1uF
C15 "GCM188R71E104KA57D" 0603 59.365,65.589 r180 top value=0.1uF
C16 "CL32B226KOJNFNE" 1210_270 132.358,24.067 r270 top value=22uF
C17 "C3216X7R1A106K085AC" 1206 134.922,50.91 r90 top value=10uF
C18 "08055C105K4Z2A" 0805L 28.801,16.561 r270 top value=1uF
C19 "CGA4J3X7R1H225K125AB" 0805L 31.105,16.561 r270 top value=2.2uF
C20 "08055C105K4Z2A" 0805_HV 32.85,23.072 r180 top value=1uF
C21 "08055C105K4Z2A" 0805L 50.497,26.718 r270 top value=1uF
C22 "C0603C104K5RACAUTO" 0603L 33.675,30.454 r90 top value=0.1uF
C23 "C3216X7R1A106K085AC" 1206 132.101,50.91 r90 top value=10uF
C24 "08055C105K4Z2A" 0805L 50.497,17.81 r270 top value=1uF
C25 "08055C105K4Z2A" 0805L 28.65,51.609 r270 top value=1uF
C26 "CGA4J3X7R1H225K125AB" 0805L 30.904,51.609 r270 top value=2.2uF
C27 "08055C105K4Z2A" 0805_HV 32.801,57.334 r180 top value=1uF
C28 "08055C105K4Z2A" 0805L 50.605,61.1 r270 top value=1uF
C29 "C0603C104K5RACAUTO" 0603L 33.399,64.825 r90 top value=0.1uF
C30 "C3216X7R1A106K085AC" 1206 135.576,23.983 r270 top value=10uF
C31 "08055C105K4Z2A" 0805L 50.497,52.102 r270 top value=1uF
C32 "C3216X7R1A106K085AC" 1206 132.621,24.967 r270 bottom value=10uF
C33 "885012207025" 0805_HV 128.13,36.95 r180 bottom value=4.7uF
C34 "885012207025" 0805_HV 137.949,36.95 r0 bottom value=4.7uF
C35 "885012207025" 0805_HV 138.402,34.716 r0 bottom value=4.7uF
C36 "885012207025" 0805_HV 127.605,34.696 r180 bottom value=4.7uF
C37 "GRM21BR71A225KA01L" 0805_HV 128.157,41.419 r180 bottom value=2.2uF
C38 "GRM21BR71A225KA01L" 0805_HV 137.949,39.177 r0 bottom value=2.2uF
C39 "GRM21BR71A225KA01L" 0805_HV 128.157,39.177 r180 bottom value=2.2uF
C40 "2R5TPE1500MF" 7343-40 107.119,18.76 r270 top value=1500uF
C41 "2R5TPE1500MF" 7343-40 107.119,69.271 r90 top value=1500uF
C42 "2R5TPE1500MF" 7343-40 102.033,50.877 r270 top value=1500uF
C43 "2R5TPE1500MF" 7343-40 107.119,50.86 r270 top value=1500uF
C44 "2R5TPE1500MF" 7343-40 112.367,69.271 r90 top value=1500uF
C45 "2R5TPE1500MF" 7343-40 101.87,69.271 r90 top value=1500uF
C46 "2R5TPE1500MF" 7343-40 112.367,50.86 r270 top value=1500uF
C47 "2R5TPE1500MF" 7343-40 101.87,18.76 r270 top value=1500uF
C48 "2R5TPE1500MF" 7343-40 107.119,36.584 r90 top value=1500uF
C49 "2R5TPE1500MF" 7343-40 101.958,36.584 r90 top value=1500uF
C50 "2R5TPE1500MF" 7343-40 112.367,36.584 r90 top value=1500uF
C51 "C0805C105K4RACAUTO" 0805_HV 128.13,45.94 r180 bottom value=1uF
C52 "C0805C105K4RACAUTO" 0805_HV 128.142,43.68 r180 bottom value=1uF
C53 "C0805C105K4RACAUTO" 0805_HV 137.949,45.646 r0 bottom value=1uF
C54 "C0805C105K4RACAUTO" 0805_HV 137.949,43.68 r0 bottom value=1uF
C55 "06031C102KAT2A" 0603 64.232,72.961 r90 top value=1000pF
C56 "12061C102KAT2A" 1206 61.698,72.919 r90 top value=1000pF
C57 "06031C102KAT2A" 0603 66.177,72.96 r90 top value=1000pF
C58 "06031C102KAT2A" 0603 68.116,72.96 r90 top value=1000pF
C59 "12061C102KAT2A" 1206 70.626,72.955 r90 top value=1000pF
C60 "12061C102KAT2A" 1206 61.54,37.894 r90 top value=1000pF
C61 "06031C102KAT2A" 0603 64.109,37.881 r90 top value=1000pF
C62 "06031C102KAT2A" 0603 66.177,37.87 r90 top value=1000pF
C63 "06031C102KAT2A" 0603 68.116,37.881 r90 top value=1000pF
C64 "12061C102KAT2A" 1206 70.636,37.894 r90 top value=1000pF
C65 "C0805C105K4RACAUTO" 0805_HV 137.949,41.419 r0 bottom value=1uF
C66 "T541X227M016AH6710" FP-T541X227M016AH6710_2917-MFG 45.919,37.946 r270 top value=220µF
C67 "T541X227M016AH6710" FP-T541X227M016AH6710_2917-MFG 74.796,37.848 r270 top value=220µF
C68 "T541X227M016AH6710" FP-T541X227M016AH6710_2917-MFG 80.334,37.848 r270 top value=220µF
C69 "T541X227M016AH6710" FP-T541X227M016AH6710_2917-MFG 46.268,72.811 r270 top value=220µF
C70 "T541X227M016AH6710" FP-T541X227M016AH6710_2917-MFG 57.174,37.946 r270 top value=220µF
C71 "T541X227M016AH6710" FP-T541X227M016AH6710_2917-MFG 51.614,37.946 r270 top value=220µF
C72 "T541X227M016AH6710" FP-T541X227M016AH6710_2917-MFG 80.279,73.055 r270 top value=220µF
C73 "T541X227M016AH6710" FP-T541X227M016AH6710_2917-MFG 51.896,72.811 r270 top value=220µF
C74 "T541X227M016AH6710" FP-T541X227M016AH6710_2917-MFG 57.523,72.811 r270 top value=220µF
C75 "T541X227M016AH6710" FP-T541X227M016AH6710_2917-MFG 74.74,73.005 r270 top value=220µF
C76 "2R5TPE1500MF" 7343-40 112.367,18.76 r270 top value=1500uF
C77 "C0805C105K4RACAUTO" 0805_HV 127.38,48.377 r180 bottom value=1uF
C78 "12061C102KAT2A" 1206L 87.543,66.984 r180 top value=1000pF
C79 "C1206C103KARACTU" 1206L 87.543,69.71 r180 top value=0.01uF
C80 "C1206C103KARACTU" 1206L 87.543,52.075 r180 top value=0.01uF
C81 "GRM31CR72E104KW03L" 1206_180 87.732,49.677 r180 top value=0.1uF
C82 "GRM31CR72E104KW03L" 1206_180 87.732,47.355 r180 top value=0.1uF
C83 "12061C102KAT2A" 1206L 87.277,35.778 r180 top value=1000pF
C84 "C1206C103KARACTU" 1206L 87.277,33.052 r180 top value=0.01uF
C85 "C1206C103KARACTU" 1206L 87.277,18.058 r180 top value=0.01uF
C86 "GRM31CR72E104KW03L" 1206_180 87.466,15.66 r180 top value=0.1uF
C87 "GRM31CR72E104KW03L" 1206_180 87.466,13.337 r180 top value=0.1uF
C88 "C0603C474K8RACTU" 0603 138.366,32.838 r0 bottom value=0.47uF
C89 "08055A222JAT2A" 0805_HV 148.496,64.853 r90 top value=2200pF
C90 "2R5TPE1500MF" 7343-40 117.616,50.86 r270 top value=1500uF
C91 "2R5TPE1500MF" 7343-40 117.616,69.271 r90 top value=1500uF
C92 "2R5TPE1500MF" 7343-40 117.616,36.584 r90 top value=1500uF
C93 "2R5TPE1500MF" 7343-40 117.616,18.76 r270 top value=1500uF
C94 "2R5TPE1500MF" 7343-40 101.87,80.068 r270 top value=1500uF
C95 "2R5TPE1500MF" 7343-40 107.119,80.068 r270 top value=1500uF
C96 "2R5TPE1500MF" 7343-40 117.616,80.068 r270 top value=1500uF
C97 "2R5TPE1500MF" 7343-40 122.612,80.068 r270 top value=1500uF
C98 "2R5TPE1500MF" 7343-40 101.87,7.97 r90 top value=1500uF
C99 "2R5TPE1500MF" 7343-40 107.119,7.97 r90 top value=1500uF
C100 "2R5TPE1500MF" 7343-40 112.367,7.97 r90 top value=1500uF
C101 "2R5TPE1500MF" 7343-40 122.612,18.76 r270 top value=1500uF
C102 "2R5TPE1500MF" 7343-40 127.595,7.97 r90 top value=1500uF
C103 "2R5TPE1500MF" 7343-40 127.595,80.068 r270 top value=1500uF
C104 "2R5TPE1500MF" 7343-40 122.612,7.97 r90 top value=1500uF
C105 "2R5TPE1500MF" 7343-40 117.616,7.97 r90 top value=1500uF
C106 "2R5TPE1500MF" 7343-40 112.367,80.068 r270 top value=1500uF
C107 "2R5TPE1500MF" 7343-40 122.612,36.574 r90 top value=1500uF
C108 "2R5TPE1500MF" 7343-40 122.612,50.86 r270 top value=1500uF
C109 "2R5TPE1500MF" 7343-40 122.612,69.286 r90 top value=1500uF
C110 "0603ZC103KAT2A" 0603 79.714,55.561 r270 top value=0.01uF
C111 "0603ZC103KAT2A" 0603 79.631,21.291 r270 top value=0.01uF
C112 "C0603C474K8RACTU" 0603 127.914,32.785 r180 bottom value=0.47uF
C113 "C0603C474K8RACTU" 0603 137.298,31.184 r0 bottom value=0.47uF
C114 "C0603C474K8RACTU" 0603 128.714,31.184 r180 bottom value=0.47uF
C115 "C0603C474K8RACTU" 0603 137.314,29.601 r0 bottom value=0.47uF
C116 "C0603C474K8RACTU" 0603 128.714,29.601 r180 bottom value=0.47uF
C117 "885012206020" 0603 138.249,27.77 r0 bottom value=0.1uF
C118 "885012206020" 0603 127.75,27.765 r180 bottom value=0.1uF
C119 "885012206020" 0603 136.509,25.022 r270 bottom value=0.1uF
C120 "885012206020" 0603 128.746,25.08 r270 bottom value=0.1uF
C121 "885012206020" 0603 134.851,25.022 r270 bottom value=0.1uF
C122 "885012206020" 0603 130.469,25.022 r270 bottom value=0.1uF
C123 "GCM188R71E104KA57D" 0603 71.926,65.685 r0 top value=0.1uF
C124 "GCM188R71E104KA57D" 0603 71.926,67.329 r0 top value=0.1uF
C125 "GCM188R71E104KA57D" 0603 59.365,31.332 r180 top value=0.1uF
C126 "GCM188R71E104KA57D" 0603 71.926,32.92 r0 top value=0.1uF
C127 "GCM188R71E104KA57D" 0603 71.926,31.33 r0 top value=0.1uF
C128 "GCM188R71E104KA57D" 0603 59.365,67.227 r180 top value=0.1uF
D1 "ES3AB-13-F" SMB 28.669,24.757 r270 top value=50V
D2 "BZT52B13-E3-08" FP-BZT52B13-E3-08_SOD123-MFG 33.717,26.423 r270 top
D5 "ES3AB-13-F" SMB 28.429,59.854 r270 top value=50V
D6 "BZT52B13-E3-08" FP-BZT52B13-E3-08_SOD123-MFG 33.542,60.667 r270 top
D7 "SK5COA" FP-NRVBA340T3G_SMA-MFG 83.059,15.701 r270 top
D8 "SK5COA" FP-NRVBA340T3G_SMA-MFG 83.219,49.677 r270 top
FID1 "Fiducial" Fiducial10-20#1 13,87.7 r0 top
FID2 "Fiducial" Fiducial10-20#2 13.1,1.2 r90 top
FID3 "Fiducial" Fiducial10-20#2 150.888,87.254 r90 top
GND "1929517" FP-1929517_HDR2-MFG 151.675,46.43 r90 top
GND1 "GND" Keystone5001 24.274,48.795 r90 top
GND2 "GND" Keystone5001 58.99,45.887 r90 top
GND3 "GND" Keystone5001 59.474,14.2 r90 top
GND4 "GND" Keystone5001 139.941,59.467 r90 top
GND5 "GND" Keystone5001 152.248,79.63 r90 top
H1 "NY PMS 440 0025 PH" "NY PMS 440 0025 PH" 159.206,83.383 r0 top
H2 "NY PMS 440 0025 PH" "NY PMS 440 0025 PH" 5.1,83.9 r0 top
H3 "NY PMS 440 0025 PH" "NY PMS 440 0025 PH" 159.106,5 r0 top
H4 "NY PMS 440 0025 PH" "NY PMS 440 0025 PH" 5,5 r0 top
H5 "1902C" Keystone_1902C 5.009,5 r180 bottom
H6 "1902C" Keystone_1902C 5.109,83.9 r180 bottom
H7 "1902C" Keystone_1902C 159.115,5 r180 bottom
H8 "1902C" Keystone_1902C 159.215,83.383 r180 bottom
J1 "SW" Tek_131-5031-00 76.606,11.426 r90 top
J2 "SW" Tek_131-5031-00 77.096,45.766 r90 top
J3 "CONSMA002-G" Linx_CONSMA002-G 159.376,73.754 r180 top
J4 "SW" Tek_131-5031-00 133.087,30.486 r0 top
J5 "SW" Tek_131-5031-00 133.045,59.213 r0 top
L1 "XAL1010-451MEB" FP-XAL1010-451MEB_SMD2-MFG 86.84,25.568 r0 top value=0.45uH
L2 "XAL1010-451MEB" FP-XAL1010-451MEB_SMD2-MFG 87,59.444 r0 top value=0.45uH
LBL1 "THT-14-423-10" Label_650x200 29.292,8.171 r0 top
Logo1 "CAUTION HOT SURFACE" IEC_HotSurface_Small 54.512,3.779 r90 top
Logo3 "FCC disclaimer" FCC_disclaimer_stacked 39.439,6.354 r0 top
Logo4 "WEEE logo" WEEE_Minimum 68.858,3.843 r90 top
Logo5 "CAUTION.  READ USER GUIDE BEFORE USE" IEC_Caution_Small 61.308,3.919 r90 top
Q1 "EPC7019GC" FP-EPC7019GC_FSMD-G-MFG 65.8,30.065 r180 top
Q3 "EPC7019GC" FP-EPC7019GC_FSMD-G-MFG 57.144,22.699 r180 top
Q4 "EPC7019GC" FP-EPC7019GC_FSMD-G-MFG 65.875,22.699 r180 top
Q6 "EPC7019GC" FP-EPC7019GC_FSMD-G-MFG 65.8,64.193 r180 top
Q7 "EPC7019GC" FP-EPC7019GC_FSMD-G-MFG 57.061,57.056 r180 top
Q8 "EPC7019GC" FP-EPC7019GC_FSMD-G-MFG 65.792,57.056 r180 top
Q9 "EPC7019GC" FP-EPC7019GC_FSMD-G-MFG 74.607,22.699 r180 top
Q10 "EPC7019GC" FP-EPC7019GC_FSMD-G-MFG 74.524,57.056 r180 top
Q11 "CSD16408Q5" DQH0008A 133.019,44.486 r270 bottom value=25V
R1 "RMCF0603ZT0R00" 0603L 139.799,85.322 r0 top value=0
R2 "RC0603FR-0749K9L" 0603L 142.106,82.641 r90 top value=49.9k
R3 "RC0603FR-0710RL" 0603L 141.766,66.844 r180 bottom value=10.0
R4 "RC0603FR-0749R9L" 0603L 153.4,64.486 r270 top value=49.9
R5 "RMCF0603ZT0R00" 0603L 143.67,67.697 r90 bottom value=0
R6 "RC0603FR-073K09L" 0603L 142.916,77.767 r180 bottom value=3.09k
R7 "RG1608P-103-B-T5" 0603L 150.24,65.357 r270 top value=10.0k
R8 "RC0603FR-07392KL" 0603L 146.347,76.465 r270 bottom value=392k
R9 "CRCW060318K7FKEA" 0603 149.236,69.103 r180 top value=18.7k
R10 "RG1608P-3322-B-T5" 0603L 146.728,64.217 r90 top value=33.2k
R11 "RT0603DRE0749K9L" 0603L 147.825,80.318 r270 top value=49.9k
R12 "RMCF0603ZT0R00" 0603L 143.516,76.433 r180 bottom value=0
R13 "RT0603DRE0749K9L" 0603L 143.58,64.217 r90 top value=49.9k
R14 "RMCF0603ZT0R00" 0603L 33.63,17.298 r0 top value=0
R15 "RT0805BRD0741K2L" 0805L 37.826,20.644 r180 bottom value=41.2k
R16 "RT0805BRD0741K2L" 0805L 37.876,18.229 r180 bottom value=41.2k
R17 "RT0603BRD071K5L" 0603 84.877,22.095 r0 bottom value=1.50k
R18 "RMCF0603ZT0R00" 0603L 33.521,51.352 r0 top value=0
R19 "RT0805BRD0741K2L" 0805L 37.45,55.034 r180 bottom value=41.2k
R20 "RT0805BRD0741K2L" 0805L 37.45,52.752 r180 bottom value=41.2k
R21 "RT0603BRD071K5L" 0603 85.037,56.885 r0 bottom value=1.50k
R23 "RCS06032R00FKEA" FP-RCS06032R00FKEA_0603-MFG 32.941,19.525 r90 top value=2
R24 "RMCF0603ZT0R00" 0603L 28.507,19.228 r180 top value=0
R28 "KRL6432E-M-R007-F-T1" 2512_WIDE 95.16,18.56 r0 top value=0.007
R29 "KRL6432E-M-R007-F-T1" 2512_WIDE 95.11,25.639 r0 top value=0.007
R30 "KRL6432E-M-R007-F-T1" 2512_WIDE 95.092,32.692 r0 top value=0.007
R31 "KRL6432E-M-R007-F-T1" 2512_WIDE 95.092,52.687 r0 top value=0.007
R32 "KRL6432E-M-R007-F-T1" 2512_WIDE 95.092,59.741 r0 top value=0.007
R33 "KRL6432E-M-R007-F-T1" 2512_WIDE 95.092,66.807 r0 top value=0.007
R45 "RCS06032R00FKEA" FP-RCS06032R00FKEA_0603-MFG 32.842,53.325 r90 top value=2
R46 "RMCF0603ZT0R00" 0603L 27.729,54.284 r180 top value=0
R67 "RT0603BRD07931RL" 0603 151.773,64.459 r90 top value=931
R68 "RCG060310K0FKEA" 0603L 48.2,33.1 r0 top value=10.0k
R69 "RCG060310K0FKEA" 0603L 48.567,21.699 r90 bottom value=10.0k
R70 "CRCW06033R00JNEA" 0603 63.563,27.064 r90 bottom value=3.0
R71 "RMCF0603ZT0R00" 0603L 62.171,28.513 r270 bottom value=0
R74 "RMCF0603ZT0R00" 0603L 54.274,19.713 r90 bottom value=0
R75 "RMCF0603ZT0R00" 0603L 53.068,21.888 r270 bottom value=0
R76 "RMCF0603ZT0R00" 0603L 63.005,19.713 r90 bottom value=0
R77 "RMCF0603ZT0R00" 0603L 61.464,21.888 r270 bottom value=0
R78 "RMCF0603ZT0R00" 0603L 71.73,19.713 r90 bottom value=0
R79 "RMCF0603ZT0R00" 0603L 70.304,21.888 r270 bottom value=0
R81 "RCG060310K0FKEA" 0603L 48.581,67.227 r0 top value=10.0k
R82 "RCG060310K0FKEA" 0603L 48.567,56.46 r90 bottom value=10.0k
R83 "CRCW06033R00JNEA" 0603 63.563,61.278 r90 bottom value=3.0
R84 "RMCF0603ZT0R00" 0603L 62.171,62.69 r270 bottom value=0
R87 "RMCF0603ZT0R00" 0603L 54.288,54.031 r90 bottom value=0
R88 "RMCF0603ZT0R00" 0603L 53.024,56.686 r270 bottom value=0
R89 "RMCF0603ZT0R00" 0603L 62.776,54.031 r90 bottom value=0
R90 "RMCF0603ZT0R00" 0603L 61.448,56.405 r270 bottom value=0
R91 "RMCF0603ZT0R00" 0603L 71.63,54.031 r90 bottom value=0
R92 "RMCF0603ZT0R00" 0603L 70.196,56.405 r270 bottom value=0
R94 "RCS06030000Z0EA" 0603L 137.31,47.268 r180 bottom value=0
R95 "PHT0603Y1002BGT200" 0603L 137.86,49.191 r270 bottom value=10.0k
R96 "WSL2512R0400FEA18" 2512 135.218,51.923 r270 bottom value=0.04
R97 "WSL2512R0400FEA18" 2512 131.381,51.923 r270 bottom value=0.04
R99 "RC0603FR-071ML" 0603L 144.486,81.321 r90 top value=1.00Meg
R100 "VMS-R500-1.0-U" FP-VMS-R500-1.0-U_2512-MFG 76.636,51.623 r0 top value=0.5
R101 "VMS-R500-1.0-U" FP-VMS-R500-1.0-U_2512-MFG 76.606,17.385 r0 top value=0.5
TP3 "OUTA" Keystone5002 137.524,73.492 r90 top
TP4 "OUTB" Keystone5002 137.524,77.242 r90 top
TP5 "BODE" Keystone5002 154.771,68.172 r180 top
TP7 "0V8" Keystone5000 154.771,60.215 r180 top
TP8 "12V" Keystone5000 24.274,53.749 r90 top
TP10 "12V" Keystone5000 29.707,35.068 r90 top
TP13 "TRANS" Testpoint_Keystone_Miniature 140.4,49.663 r270 bottom
U1 "TPS7H5004HFT/EM" HFT0022A-C01-MFG 143.346,72.434 r270 top
U3 "TPS7H6023/EM" HBX0048A-IPC_C 42.292,24.239 r0 top
U4 "TPS7H6023/EM" HBX0048A-IPC_C 42.292,58.604 r0 top
Vin "GND" FP-1929517_HDR2-MFG 12.357,40.413 r270 top

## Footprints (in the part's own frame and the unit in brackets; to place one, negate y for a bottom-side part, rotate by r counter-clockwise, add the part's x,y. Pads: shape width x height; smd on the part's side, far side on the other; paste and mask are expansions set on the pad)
0603 [mm] "0603 from SM-752 data"
  rect 1x0.95 smd: 1(-0.8,0) 2(0.8,0)
  silkscreen extent -1.52,-0.69 1.52,0.69, body extent -0.87,-0.47 0.87,0.47, height 1
0603L [mm] "0603 from SM-752 data"
  rect 0.8x0.85 smd: 1(-0.7,0) 2(0.7,0)
  silkscreen extent -0.07,-0.33 0.07,0.33, body extent -0.87,-0.47 0.87,0.47, height 1
0805_HV [mil] "0805 with 30mil clearance between pads"
  rect 50x63 smd: 1(-40,0) 2(40,0)
  silkscreen extent -74,-40 74,40, body extent -43,-29 43,29, height 57
0805L [mm] "0805 from SM-752 data"
  rect 1.1x1.4 smd: 1(-0.75,0) 2(0.75,0)
  body extent -1.1,-0.72 1.1,0.72, height 1.45
1206 [mm] "1206 from SM-752 data"
  rect 1.3x1.85 smd: 1(-1.45,0) 2(1.45,0)
  silkscreen extent -2.4,-1.21 2.4,1.21, body extent -1.7,-0.9 1.7,0.9, height 1.35
1206_180 [mm] "1206_180"
  rect 1.1x1.6 smd: 1(-1.7,0) 2(1.7,0)
  silkscreen extent -0.9,-1 0.9,1, body extent -1.75,-0.95 1.75,0.95, height 1.8
1206L [mm] "1206 from SM-752 data"
  rect 1.1x1.75 smd: 1(-1.35,0) 2(1.35,0)
  silkscreen extent -0.4,-0.77 0.4,0.77, body extent -1.7,-0.9 1.7,0.9, height 1.35
1210_270 [mm] "1210"
  rect 1.3x2.7 smd: 1(-1.45,0) 2(1.45,0)
  silkscreen extent -2.32,-1.57 2.32,1.57, body extent -1.7,-1.35 1.7,1.35, height 2.7
1210_270L [mm] "1210"
  rect 1.1x2.6 smd: 1(-1.35,0) 2(1.35,0)
  silkscreen extent -0.4,-1.2 0.4,1.2, body extent -1.7,-1.35 1.7,1.35, height 2.7
2512 [mm] "Chip Resistor, Body 6.3x3.2mm, IPC Medium Density"
  rect 1.3x3.4 smd: 1(-2.95,0) 2(2.95,0)
  silkscreen extent -1.9,-1.6 1.9,1.6, body extent -3.22,-1.67 3.22,1.67, height 0.71
2512_WIDE [mm] "Ohmite recommended land pattern"
  rect 1x6.6 smd: 1(-1.6,0) 2(1.6,0)
  silkscreen extent -0.82,-3.32 0.82,3.35, body extent -1.65,-3.25 1.65,3.25, height 0.7
7343-40 [mm] "Molded, 2-Leads, Body 7.3x4.3mm, Height 4mm"
  rect 2.4x2.9 smd: 1(-3.05,0) 2(3.05,0)
  silkscreen extent -3.8,-2.25 3.8,2.25, body extent -3.8,-2.25 3.8,2.25, height 4.01
DQH0008A [mm] "TI"
  rrect39% 0.91x0.51 smd paste-0.05 mask-0.05: 1(-2.795,1.905) 2(-2.795,0.635) 3(-2.795,-0.635) 4(-2.795,-1.905) 5(2.795,-1.905) 6(2.795,-0.635) 7(2.795,0.635) 8(2.795,1.905)
  rrect9% 1.14x1.23 on Bottom Paste: 9(-1.06,-1.43) 9(-1.06,0) 9(-1.06,1.43) 9(0.28,-1.43) 9(0.28,0) 9(0.28,1.43) 9(1.62,-1.43) 9(1.62,0) 9(1.62,1.43)
  rrect2% 4.02x4.42 on Bottom Solder: 9(0.38,0)
  rrect2% 4.93x4.52 smd paste-3 mask-3: 9(0.786,0)
  silkscreen extent -3.18,-2.68 3.18,2.68, body extent -3.05,-2.55 3.05,2.55, height 1.06
FCC_disclaimer_stacked [mm]
Fiducial10-20#1 [mm]
  round 1 smd mask+0.05: 1(0,0)
  Top Layer keep-out circle w1.178: c0,0 r0.5
Fiducial10-20#2 [mm]
  round 1 smd mask+0.5: 1(0,0)
  Top Layer keep-out circle w1.178: c0,0 r0.5
FP-1929517_HDR2-MFG [mm]
  round 2.3 hole 1.5 paste-1000 mask+0: 1(-5.18,7.82) 2(4.98,7.82) 2(4.98,-2.34)
  rect 2.3x2.3 hole 1.5 paste-1000 mask+0: 1(-5.18,-2.34)
  body extent -10.36,-11.2 10.36,11.2, height 0.25
FP-BZT52B13-E3-08_SOD123-MFG [mm] "Recommended Land Pattern"
  rrect12% 0.85x0.85 smd paste+0 mask+0: 1(1.675,0) 2(-1.675,0)
  silkscreen extent -1.43,-0.85 1.43,0.85, body extent -2.2,-0.95 2.2,0.95, height 0.25
FP-EPC7019GC_FSMD-G-MFG [mm]
  rrect11% 2.184x0.914 smd paste+0 mask+0: 1(2.87,2.286) 2(-2.87,2.286) 5(0,2.286)
  rrect5% 7.95x2.057 smd paste+0 mask+0: 3(0,-1.714)
  rrect6% 7.95x1.575 smd paste+0 mask+0: 4(0,0.686)
  silkscreen extent -4.08,-3.25 4.08,3.25, body extent -4.18,-2.96 4.18,2.96, height 0.25
FP-NRVBA340T3G_SMA-MFG [mm]
  rrect5% 2x2 smd paste+0 mask+0: 1(-2,0) 2(2,0)
  silkscreen extent -4.3,-1.46 2.28,1.46, body extent -3.1,-1.56 3.1,1.56, height 0.25
FP-RCS06032R00FKEA_0603-MFG [mm]
  rrect13% 0.75x1 smd paste+0 mask+0: 1(-0.75,0) 2(0.75,0)
  silkscreen extent -0.82,-0.86 0.87,0.86, body extent -1.22,-0.6 1.22,0.6, height 0.25
FP-T541X227M016AH6710_2917-MFG [mm]
  rrect5% 1.99x2.33 smd paste+0 mask+0: 1(-3.01,0) 2(3.01,0)
  silkscreen extent -3.8,-2.3 3.8,2.3, body extent -4.13,-2.42 4.13,2.42, height 0.25
FP-VMS-R500-1.0-U_2512-MFG [mm]
  rrect6% 1.55x3.6 smd paste+0 mask+0: 1(-2.975,0) 2(2.975,0)
  silkscreen extent -1.83,-1.63 1.83,1.63, body extent -3.85,-1.9 3.85,1.9, height 0.25
FP-XAL1010-451MEB_SMD2-MFG [mm]
  rrect4% 2.38x9 smd paste+0 mask+0: 1(-3.325,0) 2(3.325,0)
  silkscreen extent -5.92,-5.9 5.25,5.9, body extent -5.35,-6 5.35,6, height 0.25
HBX0048A-IPC_C [mm]
  rrect100% 2x0.35 smd paste+0 mask+0: 1(-6.275,7.62) 2(-6.275,6.985) 3(-6.275,6.35) 4(-6.275,5.715) 5(-6.275,5.08) 6(-6.275,4.445) 7(-6.275,3.81) 8(-6.275,3.175) 9(-6.275,2.54) 10(-6.275,1.905) 11(-6.275,1.27) 12(-6.275,0.635) 13(-6.275,-0.635) 14(-6.275,-1.27) 15(-6.275,-1.905) 16(-6.275,-2.54) 17(-6.275,-3.175) 18(-6.275,-3.81) 19(-6.275,-4.445) 20(-6.275,-5.08) 21(-6.275,-5.715) 22(-6.275,-6.35) 23(-6.275,-6.985) 24(-6.275,-7.62) 25(6.275,-7.62) 26(6.275,-6.985) 27(6.275,-6.35) 28(6.275,-5.715) 29(6.275,-5.08) 30(6.275,-4.445) 31(6.275,-3.81) 32(6.275,-3.175) 33(6.275,-2.54) 34(6.275,-1.905) 35(6.275,-1.27) 36(6.275,-0.635) 37(6.275,0.635) 38(6.275,1.27) 39(6.275,1.905) 40(6.275,2.54) 41(6.275,3.175) 42(6.275,3.81) 43(6.275,4.445) 44(6.275,5.08) 45(6.275,5.715) 46(6.275,6.35) 47(6.275,6.985) 48(6.275,7.62)
  rrect2% 5.64x7.14 smd paste+0 mask+0: 49(0,4.195) 50(0,-4.195)
  silkscreen extent -7.96,-8.37 4.24,8.37, body extent -7.35,-8.6 7.35,8.6, height 0.25
HFT0022A-C01-MFG [mm]
  rrect23% 2x0.435 smd paste+0 mask+0: 1(-5.145,3.175) 2(-5.145,2.54) 3(-5.145,1.905) 4(-5.145,1.27) 5(-5.145,0.635) 6(-5.145,0) 7(-5.145,-0.635) 8(-5.145,-1.27) 9(-5.145,-1.905) 10(-5.145,-2.54) 11(-5.145,-3.175) 12(5.145,-3.175) 13(5.145,-2.54) 14(5.145,-1.905) 15(5.145,-1.27) 16(5.145,-0.635) 17(5.145,0) 18(5.145,0.635) 19(5.145,1.27) 20(5.145,1.905) 21(5.145,2.54) 22(5.145,3.175)
  rrect3% 3.62x7.29 smd paste-1000 mask+0: 23(0,0)
  silkscreen extent -6.83,-3.97 3.23,3.97, body extent -6.24,-4.07 6.24,4.07, height 0.25
IEC_Caution_Small [mm]
  silkscreen extent -2.72,-2.36 2.72,2.35
IEC_HotSurface_Small [mm]
  silkscreen extent -2.72,-2.36 2.72,2.35
Keystone5000 [mil] "For Keystone 500x miniature loop terminals"
  round 80 hole 40: 1(0,0)
  silkscreen extent -52,-52 52,52, body extent -49,-49 49,49, height 182
Keystone5001 [mil] "For Keystone 500x miniature loop terminals"
  round 80 hole 40: 1(0,0)
  silkscreen extent -52,-52 52,52, body extent -49,-49 49,49, height 182
Keystone5002 [mil] "For Keystone 500x miniature loop terminals"
  round 80 hole 40: 1(0,0)
  silkscreen extent -52,-52 52,52, body extent -49,-49 49,49, height 182
Keystone_1902C [mil] "Hex Standoff, 4-40 threaded, nylon"
  round 1 on Mech4: 0(0,0)
  body extent -145,-126 146,126, height 501
Label_650x200 [mil] "Thermal Transfer Label"
  round 1 on Mech13: 0(0,0)
  silkscreen extent -325,-100 325,100, body extent -325,-100 325,100, height 1
Linx_CONSMA002-G [mm] "SMA Jack, 50 Ohm, R/A, TH"
  rrect50% 1.9x1.9 hole 1.4: 1(0,0)
  round 2 hole 1.5: 2(-2.55,2.55) 3(2.55,2.55) 4(2.55,-2.55) 5(-2.55,-2.55)
  silkscreen extent -3.5,-3.5 3.5,3.5, body extent -11.7,-3.5 3.5,3.5, height 10
"NY PMS 440 0025 PH" [mm] "4-40 nylon screw and mounting hole"
  round 8 hole 3.2: 1(0,0)
  body extent -3.3,-3.3 3.3,3.3, height 2.69
SMB [mm] "Molded Diode, 2-Leads, Body 5.4x3.6mm, IPC Medium Density, based on OnSemi component dimensions"
  rect 2.159x2.743 smd: 1(-2.21,0) 2(2.21,0)
  silkscreen extent -3.94,-2.08 3.18,2.08, body extent -2.7,-1.8 2.7,1.8, height 2.32
Tek_131-5031-00 [mil] "Tektronix cold nose probe"
  round 100 hole 68: 1(0,0)
  round 60 hole 38: 2(-100,100) 3(-100,-100) 4(100,-100) 5(100,100)
  silkscreen extent -92,-93 94,94, body extent -206,-206 206,206, height 351
Testpoint_Keystone_Miniature [mil] "Miniature SMT test point"
  rect 135x70 smd: 1(0,0)
  silkscreen extent -78,-46 78,45, body extent -52,-20 52,20, height 61
WEEE_Minimum [mm] "WEEElie bin"
  silkscreen extent -2.42,-4.38 2.52,2.65

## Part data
0V8 GND: library part CMP-0078537-1, "Fixed Terminal Blocks MKDSP 10 HV/ 2-10", Current_A=76A, Manufacturer="Phoenix Contact", Voltage_V=1kV
C1: library part CMP-0007839-2, "CAP, CERM, 0.47 uF, 50 V, +/- 10%, X5R, 0805", Cap_Case=0805, Manufacturer=TDK, Supplier Part Number 1=445-14411-1-ND, TempCo=X5R, Tolerance_%=10%, Value1="0.022012 ohm", Value2=50V, ValueDisplayed=0.47uF
C2 C9: library part CMP-0079607-1, "CAP, CERM, 1 µF, 16 V,+/- 10%, X7R, AEC-Q200 Grade 1, 0603", Cap_Case=0603, Manufacturer=TDK, Supplier Part Number 1=445-12539-1-ND, TempCo=X7R, Tolerance_%=10%, Value2=16V, ValueDisplayed=1µF
C3: library part CMP-0009226-3, "CAP, CERM, 10 uF, 50 V, +/- 10%, X7R, 1210", Cap_Case=1210, Manufacturer=MuRata, Supplier Part Number 1=490-6544-1-ND, TempCo=X7R, Tolerance_%=10%, Value1=Unknown, Value2=50V, ValueDisplayed=10uF
C4 C7 C22 C29: library part CMP-0079602-1, "CAP, CERM, 0.1 µF, 50 V,+/- 10%, X7R, AEC-Q200 Grade 1, 0603", Cap_Case=0603, Manufacturer=Kemet, Supplier Part Number 1=399-6856-1-ND, TempCo=X7R, Tolerance_%=10%, Value2=50V, ValueDisplayed=0.1µF
C5: library part CMP-0006751-4, "CAP, CERM, 100 pF, 25 V, +/- 10%, X7R, 0603", Cap_Case=0603, Manufacturer=AVX, Supplier Part Number 1=55J3899, TempCo=X7R, Tolerance_%=10%, Value1=Unknown, Value2=25V, ValueDisplayed=100pF
C6: library part CMP-0079247-1, "CAP, CERM, 4700 pF, 100 V,+/- 10%, X7R, AEC-Q200 Grade 1, 0603", Cap_Case=0603, Manufacturer=MuRata, Supplier Part Number 1=490-4930-1-ND, TempCo=X7R, Tolerance_%=10%, Value2=100V, ValueDisplayed=4700pF
C8: library part CMP-0007100-4, "CAP, CERM, 0.033 uF, 100 V, +/- 10%, X7S, AEC-Q200 Grade 1, 0603", Cap_Case=0603, Manufacturer=TDK, Supplier Part Number 1=445-6935-1-ND, TempCo=X7S, Tolerance_%=10%, Value1="0.139637 ohm", Value2=100V, ValueDisplayed=0.033uF
C10: library part CMP-0007284-4, "CAP, CERM, 82 pF, 100 V, +/- 5%, C0G/NP0, 0603", Cap_Case=0603, Manufacturer=MuRata, Supplier Part Number 1=490-1349-1-ND, TempCo=C0G/NP0, Tolerance_%=5%, Value1=Unknown, Value2=100V, ValueDisplayed=82pF
C11: library part CMP-0007082-4, "CAP, CERM, 0.01 uF, 100 V, +/- 10%, X7R, AEC-Q200 Grade 1, 0603", Cap_Case=0603, Manufacturer=TDK, Supplier Part Number 1=445-5812-1-ND, TempCo=X7R, Tolerance_%=10%, Value1="0.235428 ohm", Value2=100V, ValueDisplayed=0.01uF
C12 C13: library part CMP-0079095-1, "CAP, CERM, 0.1 µF, 50 V,+/- 10%, X7R, AEC-Q200 Grade 1, 0603", Cap_Case=0603, Manufacturer=AVX, Supplier Part Number 1=478-3540-1-ND, TempCo=X7R, Tolerance_%=10%, Value2=50V, ValueDisplayed=0.1µF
